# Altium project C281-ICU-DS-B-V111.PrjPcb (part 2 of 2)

## Sheet 06_Peripheral-C281-ICU-DS-B-V111.SchDoc: C281-ICU-DS-B-V100
size A1; Date: 2022/07/22; DrawnBy: 佟瑞泽; DocumentNumber: 6; Revision: V100; SheetNumber: 6; SheetTotal: 7
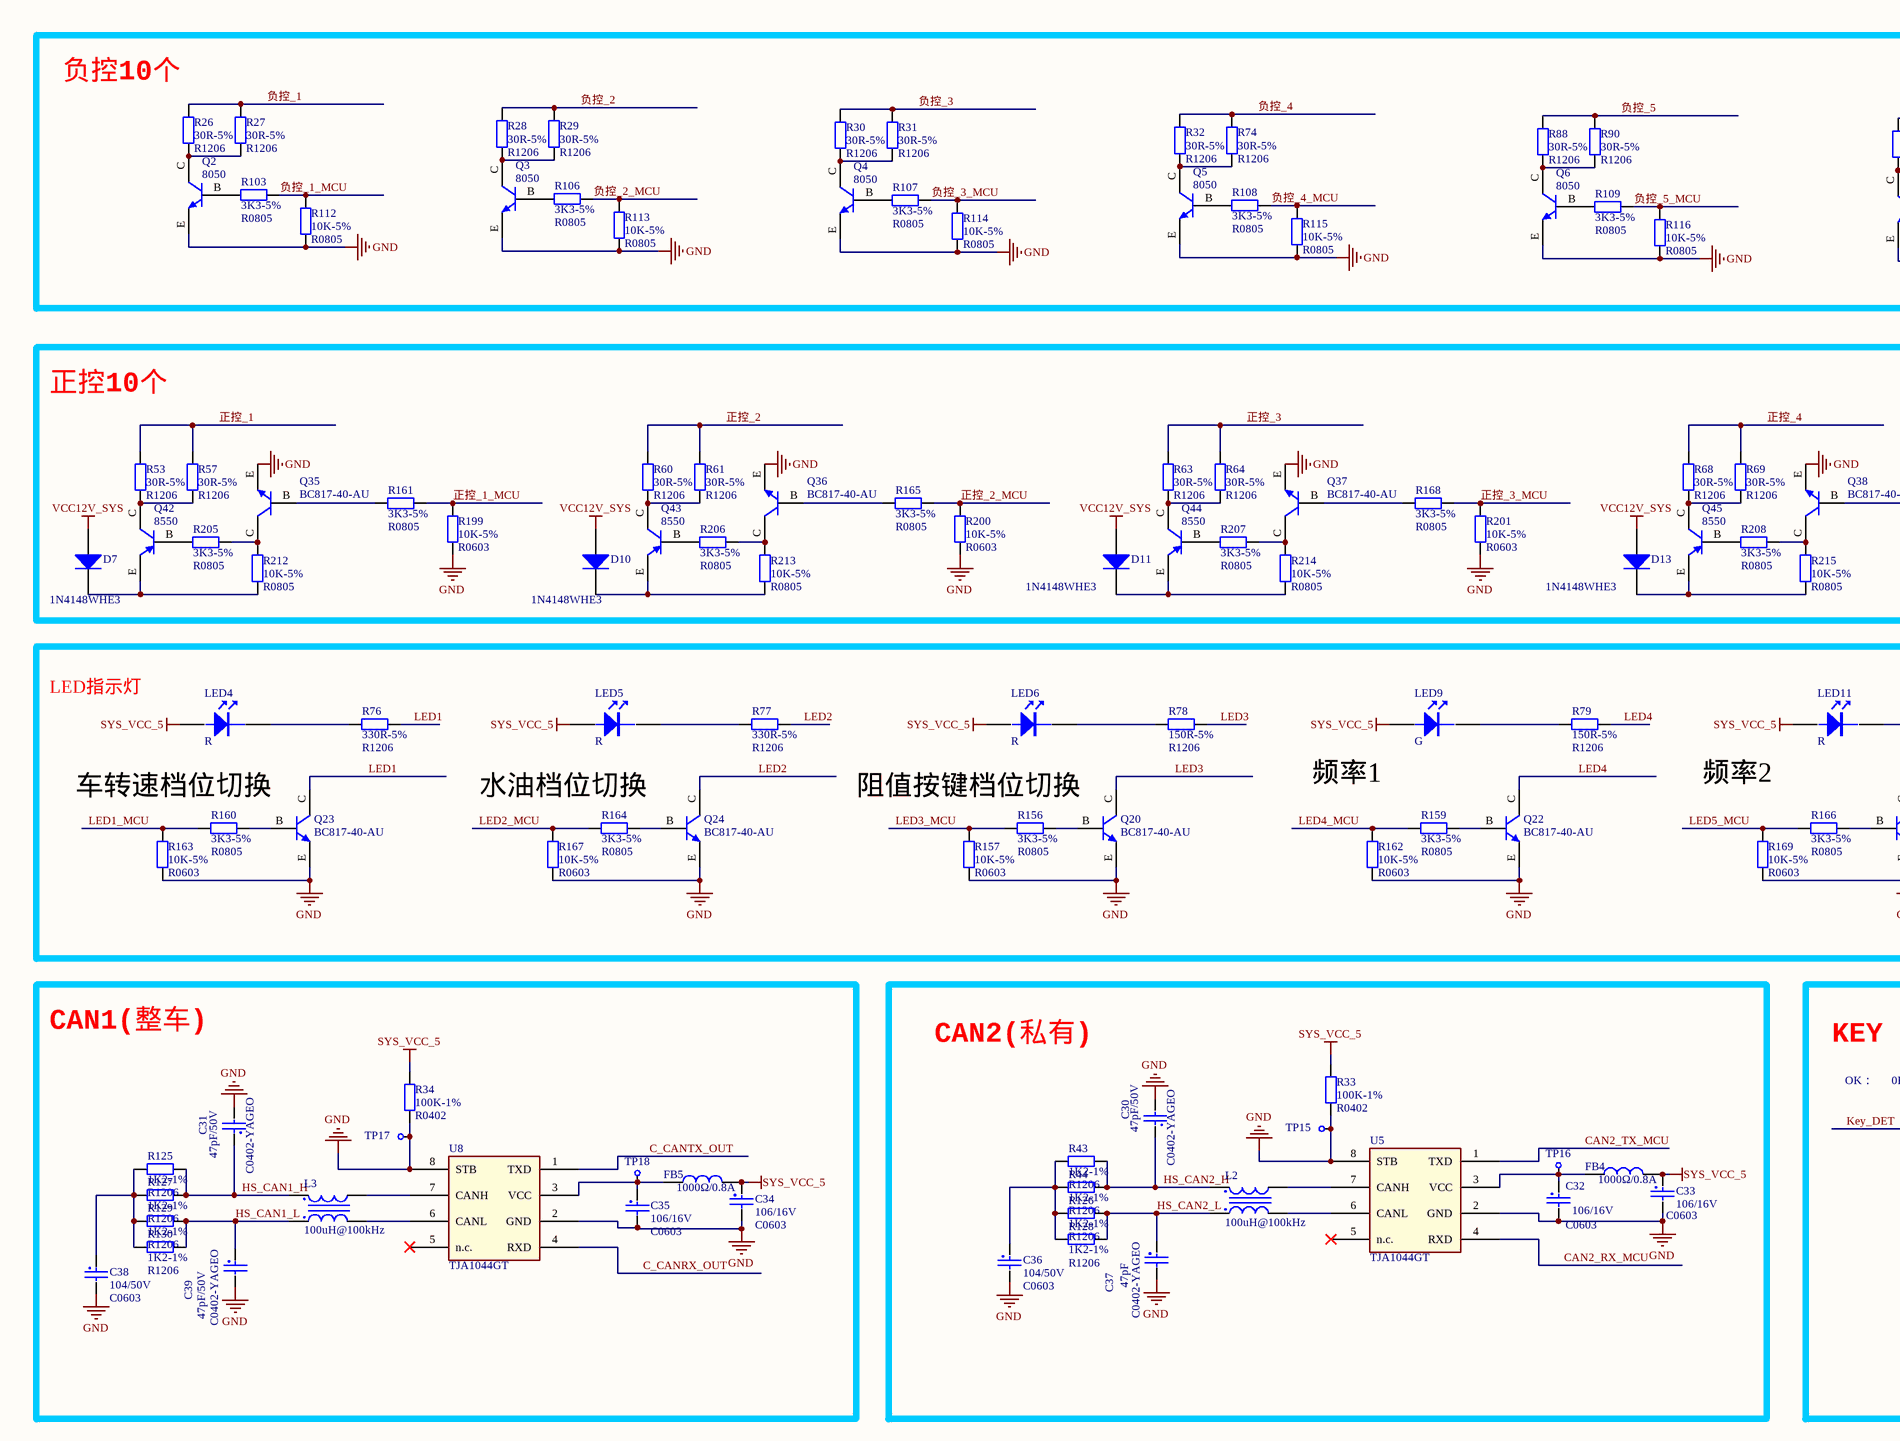
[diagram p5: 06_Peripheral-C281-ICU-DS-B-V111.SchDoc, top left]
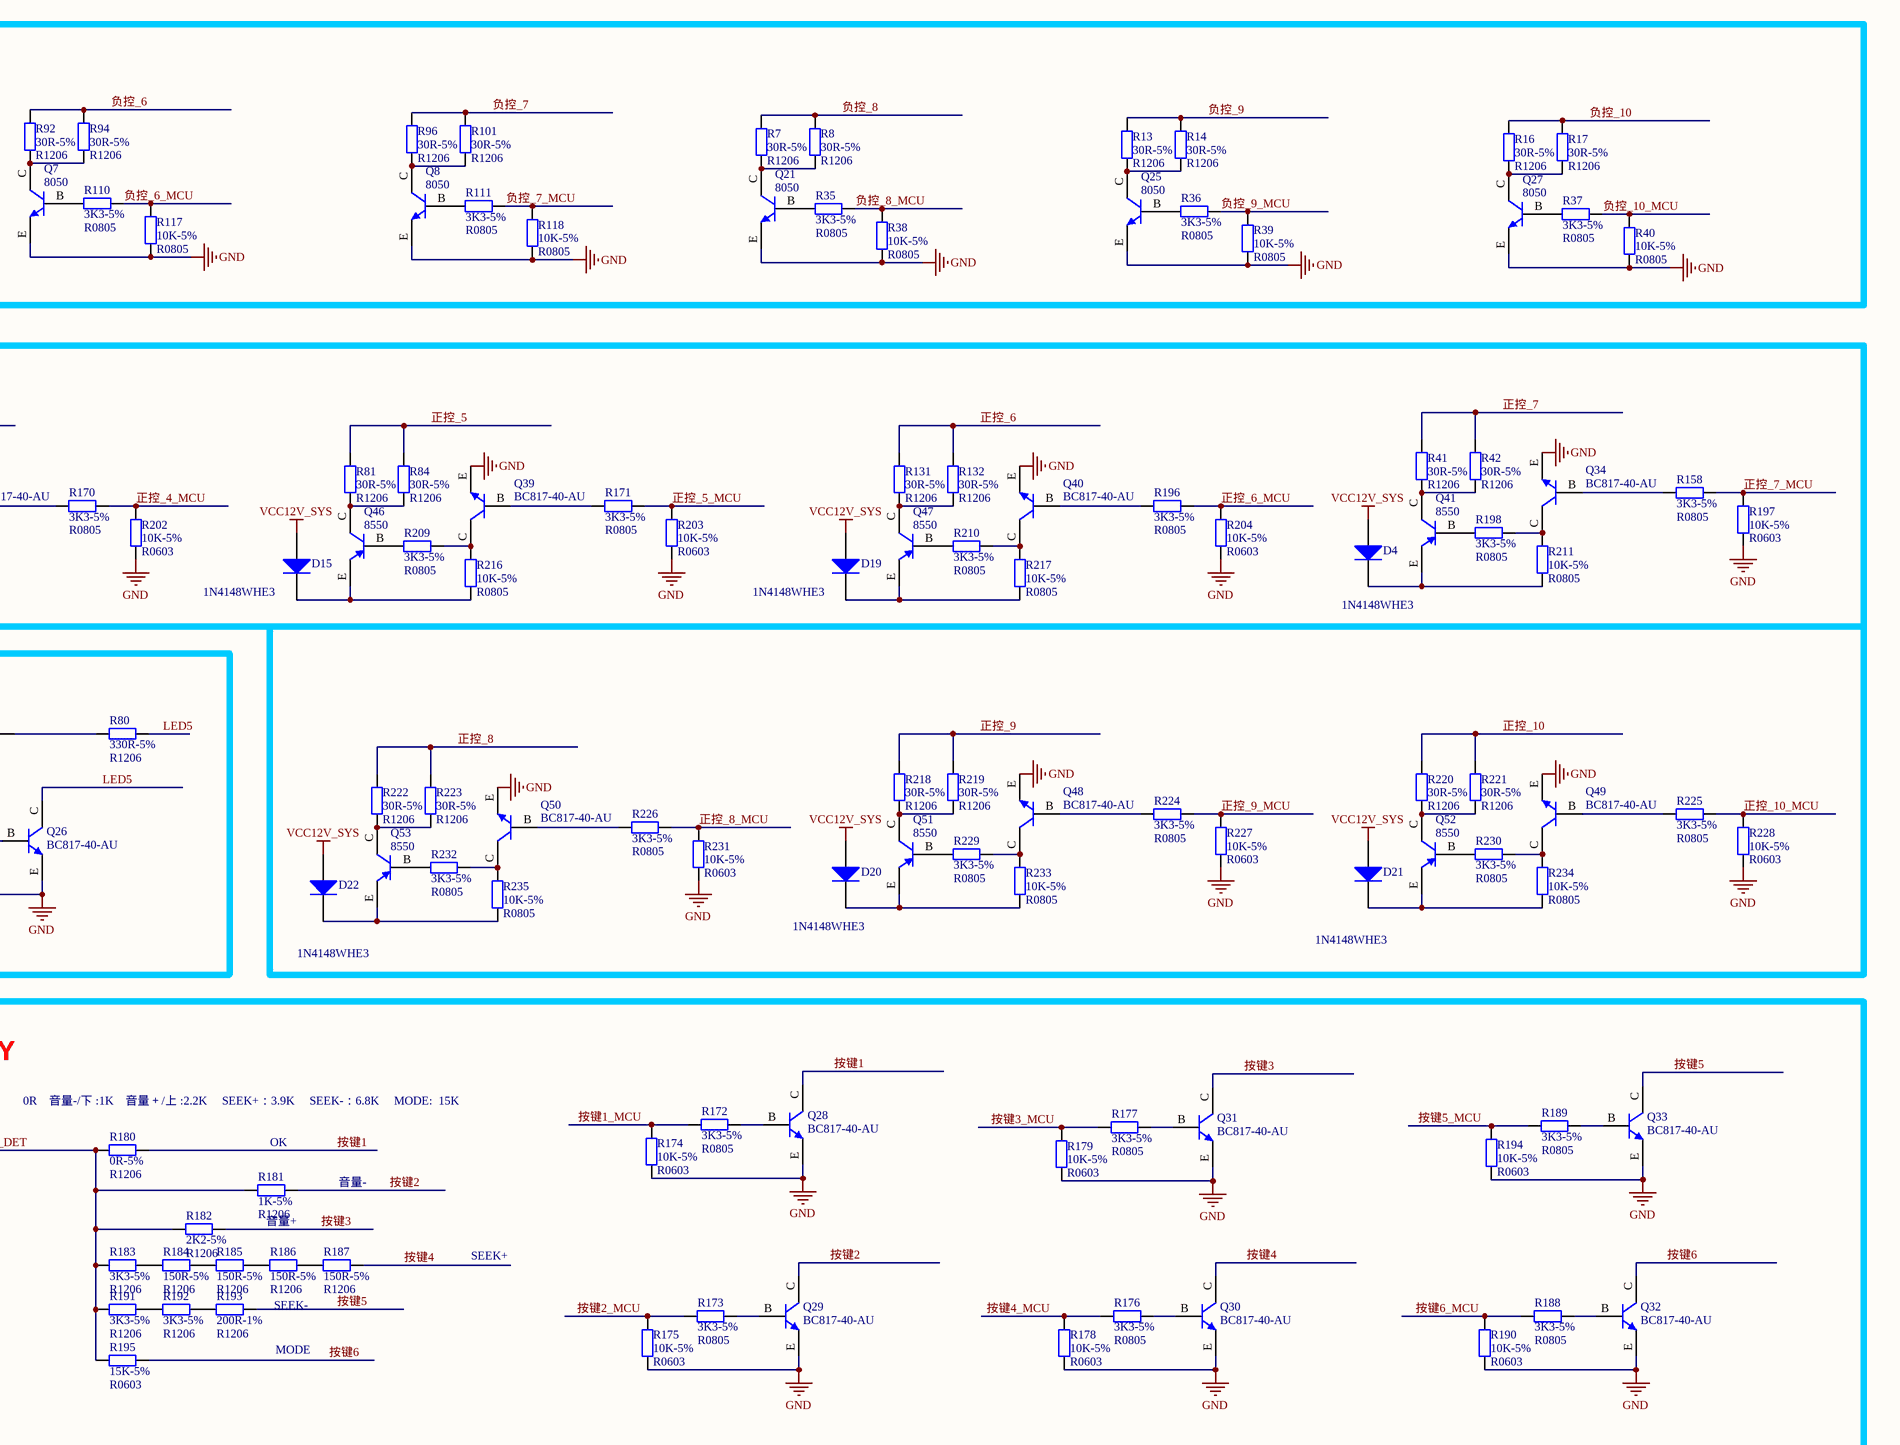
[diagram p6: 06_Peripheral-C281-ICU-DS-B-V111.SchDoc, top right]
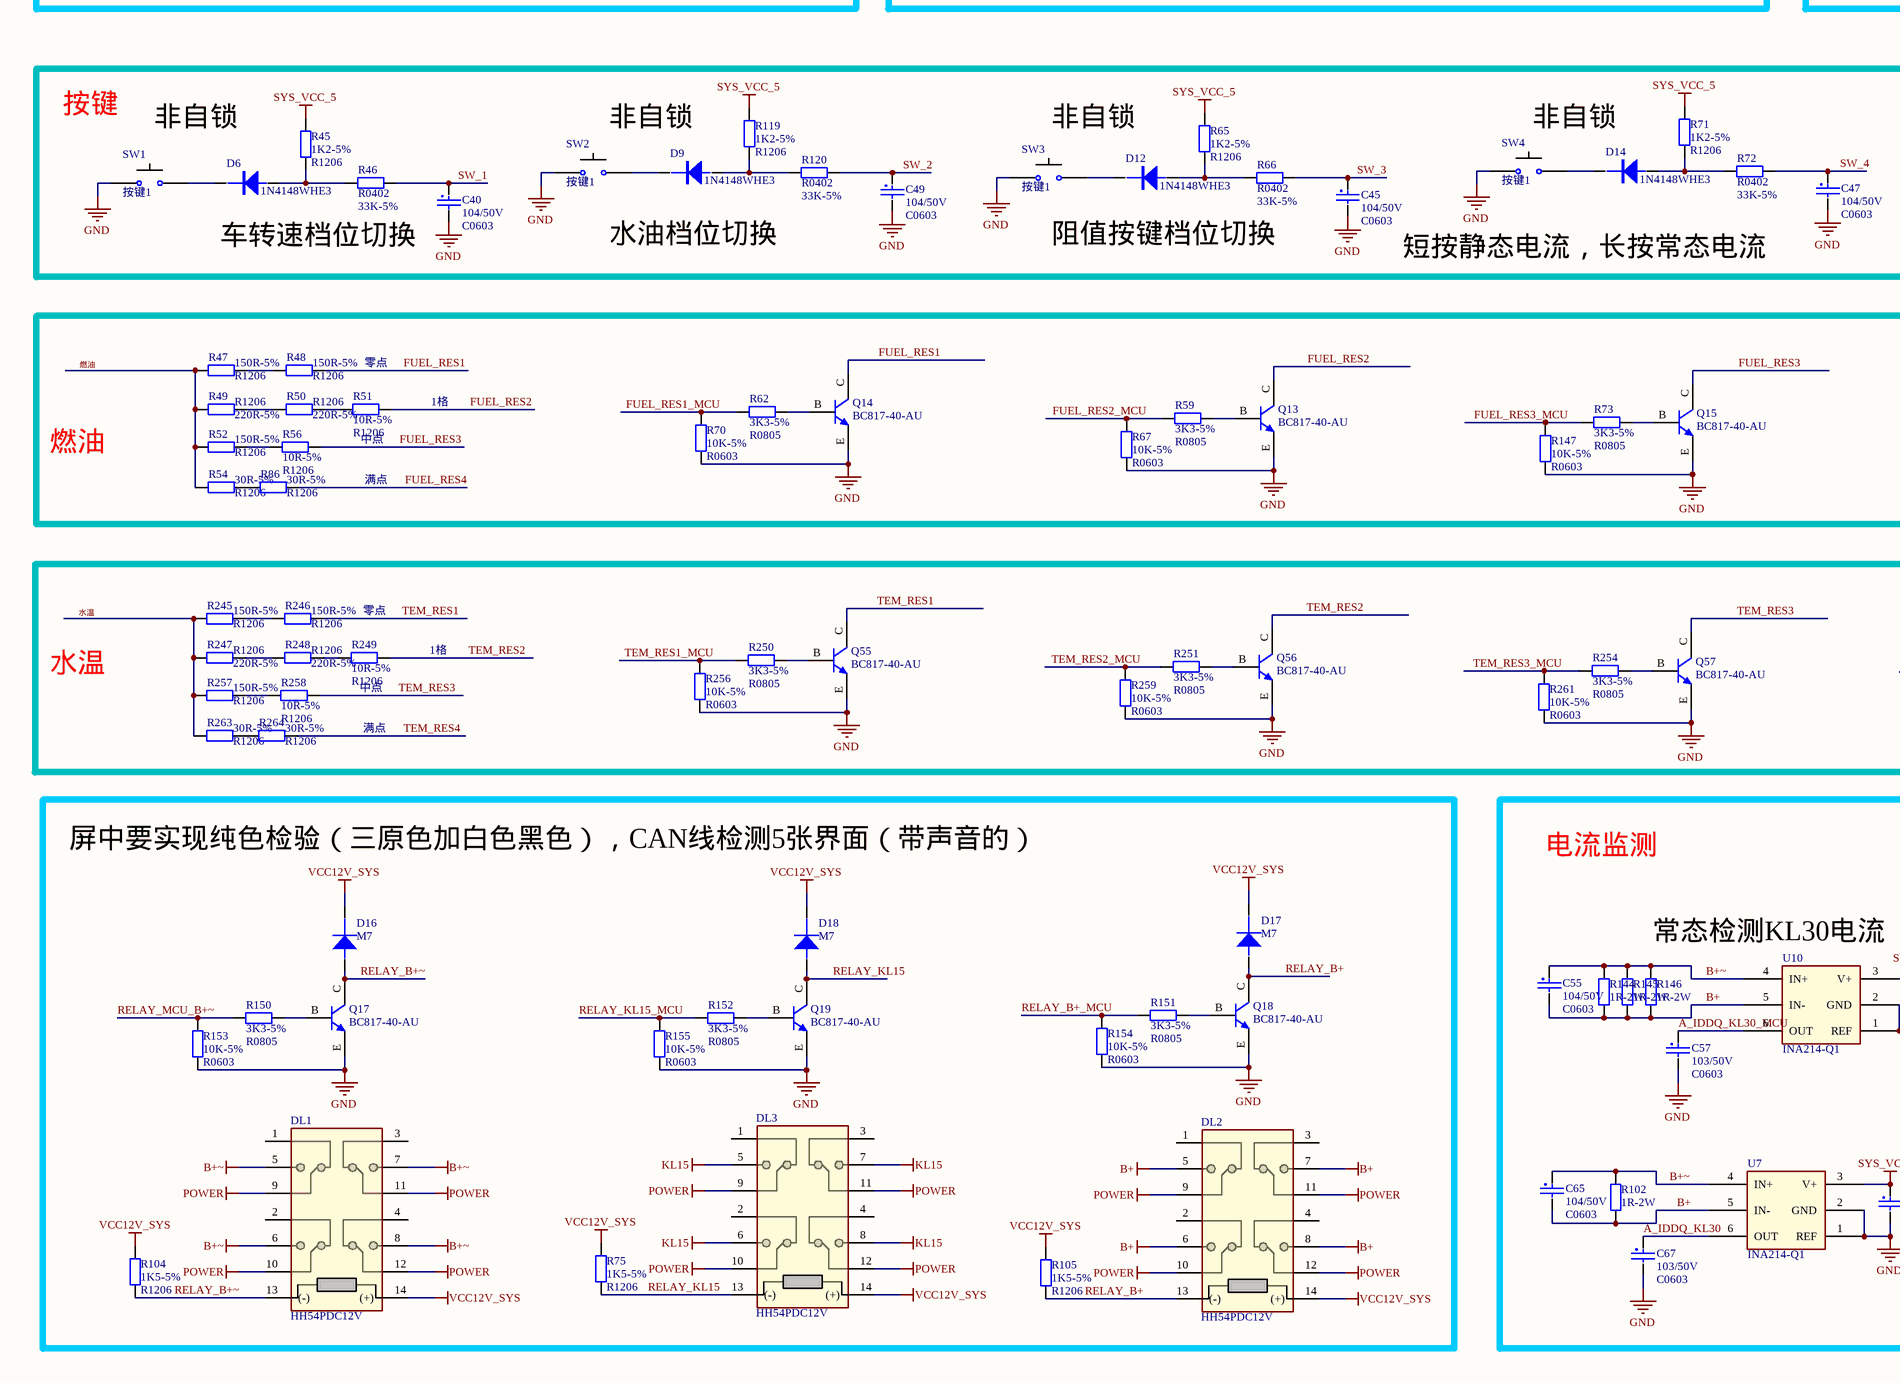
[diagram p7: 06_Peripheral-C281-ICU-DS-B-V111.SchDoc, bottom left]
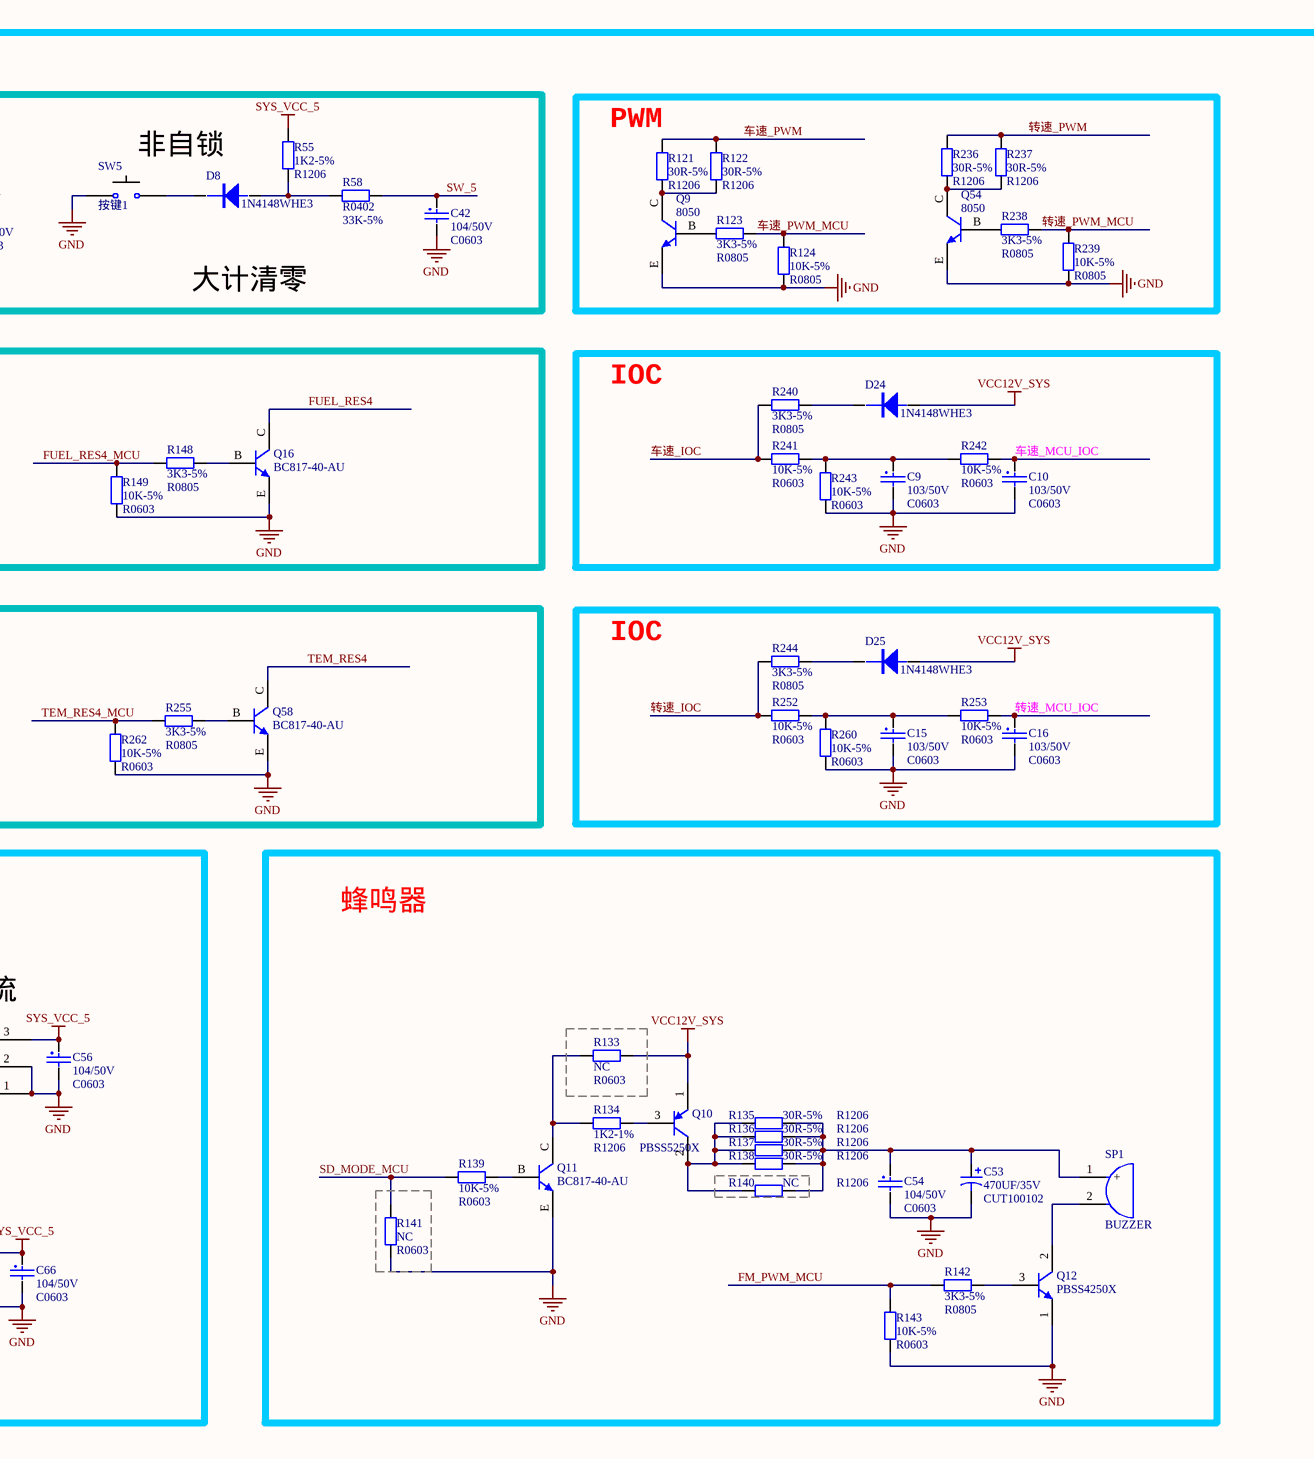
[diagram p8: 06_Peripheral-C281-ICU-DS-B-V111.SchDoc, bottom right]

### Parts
C9  value 103/50V  [C0603]  (hidden comment: 103)
C10  value 103/50V  [C0603]  (hidden comment: 103)
C15  value 103/50V  [C0603]  (hidden comment: 103)
C16  value 103/50V  [C0603]  (hidden comment: 103)
C30  value 47pF/50V  [C0402-YAGEO]  (hidden comment: 47pF)
C31  value 47pF/50V  [C0402-YAGEO]  (hidden comment: 47pF)
C32  value 106/16V  Footprint: C0603  [C0603-YAGEO]  (hidden comment: 106-16V)
C33  value 106/16V  Footprint: C0603  [C0603-YAGEO]  (hidden comment: 106-16V)
C34  value 106/16V  Footprint: C0603  [C0603-YAGEO]  (hidden comment: 106-16V)
C35  value 106/16V  Footprint: C0603  [C0603-YAGEO]  (hidden comment: 106-16V)
C36  value 104/50V  Footprint: C0603  [C0603-YAGEO]  (hidden comment: 104)
C37  47pF  [C0402-YAGEO]
C38  value 104/50V  Footprint: C0603  [C0603-YAGEO]  (hidden comment: 104)
C39  value 47pF/50V  [C0402-YAGEO]  (hidden comment: 47pF)
C40  value 104/50V  [C0603]  (hidden comment: 104)
C42  value 104/50V  [C0603]  (hidden comment: 104)
C45  value 104/50V  [C0603]  (hidden comment: 104)
C47  value 104/50V  [C0603]  (hidden comment: 104)
C49  value 104/50V  [C0603]  (hidden comment: 104)
C53  value 470UF/35V  [CUT100102]  (hidden comment: 470uF-35V)
C54  value 104/50V  [C0603]  (hidden comment: 104)
C55  value 104/50V  [C0603]  (hidden comment: 104)
C56  value 104/50V  [C0603]  (hidden comment: 104)
C57  value 103/50V  [C0603]  (hidden comment: 103)
C65  value 104/50V  [C0603]  (hidden comment: 104)
C66  value 104/50V  [C0603]  (hidden comment: 104)
C67  value 103/50V  [C0603]  (hidden comment: 103)
D4  1N4148WHE3  [SOD-123]
D6  value 1N4148WHE3  [SOD-123]  (hidden comment: 1N4148WHE3-TP)
D7  1N4148WHE3  [SOD-123]
D8  value 1N4148WHE3  [SOD-123]  (hidden comment: 1N4148WHE3-TP)
D9  value 1N4148WHE3  [SOD-123]  (hidden comment: 1N4148WHE3-TP)
D10  1N4148WHE3  [SOD-123]
D11  1N4148WHE3  [SOD-123]
D12  value 1N4148WHE3  [SOD-123]  (hidden comment: 1N4148WHE3-TP)
D13  1N4148WHE3  [SOD-123]
D14  value 1N4148WHE3  [SOD-123]  (hidden comment: 1N4148WHE3-TP)
D15  1N4148WHE3  [SOD-123]
D16  M7  [DO-214AC]
D17  M7  [DO-214AC]
D18  M7  [DO-214AC]
D19  1N4148WHE3  [SOD-123]
D20  1N4148WHE3  [SOD-123]
D21  1N4148WHE3  [SOD-123]
D22  1N4148WHE3  [SOD-123]
D24  value 1N4148WHE3  [SOD-123]  (hidden comment: 1N4148WHE3-TP)
D25  value 1N4148WHE3  [SOD-123]  (hidden comment: 1N4148WHE3-TP)
DL1  HH54PDC12V  [HH54PDC12V]
DL2  HH54PDC12V  [HH54PDC12V]
DL3  HH54PDC12V  [HH54PDC12V]
FB4  value 1000Ω/0.8A  [BLM18PG600SH1]  (hidden comment: 1000@100MHz)
FB5  value 1000Ω/0.8A  [BLM18PG600SH1]  (hidden comment: 1000@100MHz)
L2  value 100uH@100kHz  [DLW43SH101XK2]  (hidden comment: ACT45C-101-2P-TL000)
L3  value 100uH@100kHz  [DLW43SH101XK2]  (hidden comment: ACT45C-101-2P-TL000)
LED4  R  [LED]
LED5  R  [LED]
LED6  R  [LED]
LED9  G  [LED]
LED11  R  [LED]
Q2  8050  [SOT-89-3]
Q3  8050  [SOT-89-3]
Q4  8050  [SOT-89-3]
Q5  8050  [SOT-89-3]
Q6  8050  [SOT-89-3]
Q7  8050  [SOT-89-3]
Q8  8050  [SOT-89-3]
Q9  8050  [SOT-89-3]
Q10  PBSS5250X  [SOT-89]
Q11  BC817-40-AU  [SOT-23]
Q12  PBSS4250X  [SOT-89]
Q13  BC817-40-AU  [SOT-23]
Q14  BC817-40-AU  [SOT-23]
Q15  BC817-40-AU  [SOT-23]
Q16  BC817-40-AU  [SOT-23]
Q17  BC817-40-AU  [SOT-23]
Q18  BC817-40-AU  [SOT-23]
Q19  BC817-40-AU  [SOT-23]
Q20  BC817-40-AU  [SOT-23]
Q21  8050  [SOT-89-3]
Q22  BC817-40-AU  [SOT-23]
Q23  BC817-40-AU  [SOT-23]
Q24  BC817-40-AU  [SOT-23]
Q25  8050  [SOT-89-3]
Q26  BC817-40-AU  [SOT-23]
Q27  8050  [SOT-89-3]
Q28  BC817-40-AU  [SOT-23]
Q29  BC817-40-AU  [SOT-23]
Q30  BC817-40-AU  [SOT-23]
Q31  BC817-40-AU  [SOT-23]
Q32  BC817-40-AU  [SOT-23]
Q33  BC817-40-AU  [SOT-23]
Q34  BC817-40-AU  [SOT-23]
Q35  BC817-40-AU  [SOT-23]
Q36  BC817-40-AU  [SOT-23]
Q37  BC817-40-AU  [SOT-23]
Q38  BC817-40-AU  [SOT-23]
Q39  BC817-40-AU  [SOT-23]
Q40  BC817-40-AU  [SOT-23]
Q41  8550  [SOT-89-3]
Q42  8550  [SOT-89-3]
Q43  8550  [SOT-89-3]
Q44  8550  [SOT-89-3]
Q45  8550  [SOT-89-3]
Q46  8550  [SOT-89-3]
Q47  8550  [SOT-89-3]
Q48  BC817-40-AU  [SOT-23]
Q49  BC817-40-AU  [SOT-23]
Q50  BC817-40-AU  [SOT-23]
Q51  8550  [SOT-89-3]
Q52  8550  [SOT-89-3]
Q53  8550  [SOT-89-3]
Q54  8050  [SOT-89-3]
Q55  BC817-40-AU  [SOT-23]
Q56  BC817-40-AU  [SOT-23]
Q57  BC817-40-AU  [SOT-23]
Q58  BC817-40-AU  [SOT-23]
R7  value 30R-5%  [R1206]  (hidden comment: 30R)
R8  value 30R-5%  [R1206]  (hidden comment: 30R)
R13  value 30R-5%  [R1206]  (hidden comment: 30R)
R14  value 30R-5%  [R1206]  (hidden comment: 30R)
R16  value 30R-5%  [R1206]  (hidden comment: 30R)
R17  value 30R-5%  [R1206]  (hidden comment: 30R)
R26  value 30R-5%  [R1206]  (hidden comment: 30R)
R27  value 30R-5%  [R1206]  (hidden comment: 30R)
R28  value 30R-5%  [R1206]  (hidden comment: 30R)
R29  value 30R-5%  [R1206]  (hidden comment: 30R)
R30  value 30R-5%  [R1206]  (hidden comment: 30R)
R31  value 30R-5%  [R1206]  (hidden comment: 30R)
R32  value 30R-5%  [R1206]  (hidden comment: 30R)
R33  value 100K-1%  Footprint: R0402  [R0402-YAGEO]  (hidden comment: 100K-J)
R34  value 100K-1%  Footprint: R0402  [R0402-YAGEO]  (hidden comment: 100K-J)
R35  value 3K3-5%  [R0805]  (hidden comment: 3K3)
R36  value 3K3-5%  [R0805]  (hidden comment: 3K3)
R37  value 3K3-5%  [R0805]  (hidden comment: 3K3)
R38  value 10K-5%  [R0805]  (hidden comment: 10K)
R39  value 10K-5%  [R0805]  (hidden comment: 10K)
R40  value 10K-5%  [R0805]  (hidden comment: 10K)
R41  value 30R-5%  [R1206]  (hidden comment: 30R)
R42  value 30R-5%  [R1206]  (hidden comment: 30R)
R43  value 1K2-1%  Footprint: R1206  [R1206-YAGEO]  (hidden comment: 1K2-J)
R44  value 1K2-1%  Footprint: R1206  [R1206-YAGEO]  (hidden comment: 1K2-J)
R45  value 1K2-5%  [R1206]  (hidden comment: 1K2)
R46  value 33K-5%  [R0402]  (hidden comment: 33K)
R47  value 150R-5%  [R1206]  (hidden comment: 150R)
R48  value 150R-5%  [R1206]  (hidden comment: 150R)
R49  value 220R-5%  [R1206]  (hidden comment: 220R)
R50  value 220R-5%  [R1206]  (hidden comment: 220R)
R51  value 10R-5%  Footprint: R1206  [R1206-YAGEO]  (hidden comment: 10R)
R52  value 150R-5%  [R1206]  (hidden comment: 150R)
R53  value 30R-5%  [R1206]  (hidden comment: 30R)
R54  value 30R-5%  [R1206]  (hidden comment: 30R)
R55  value 1K2-5%  [R1206]  (hidden comment: 1K2)
R56  value 10R-5%  Footprint: R1206  [R1206-YAGEO]  (hidden comment: 10R)
R57  value 30R-5%  [R1206]  (hidden comment: 30R)
R58  value 33K-5%  [R0402]  (hidden comment: 33K)
R59  value 3K3-5%  [R0805]  (hidden comment: 3K3)
R60  value 30R-5%  [R1206]  (hidden comment: 30R)
R61  value 30R-5%  [R1206]  (hidden comment: 30R)
R62  value 3K3-5%  [R0805]  (hidden comment: 3K3)
R63  value 30R-5%  [R1206]  (hidden comment: 30R)
R64  value 30R-5%  [R1206]  (hidden comment: 30R)
R65  value 1K2-5%  [R1206]  (hidden comment: 1K2)
R66  value 33K-5%  [R0402]  (hidden comment: 33K)
R67  value 10K-5%  [R0603]  (hidden comment: 10K)
R68  value 30R-5%  [R1206]  (hidden comment: 30R)
R69  value 30R-5%  [R1206]  (hidden comment: 30R)
R70  value 10K-5%  [R0603]  (hidden comment: 10K)
R71  value 1K2-5%  [R1206]  (hidden comment: 1K2)
R72  value 33K-5%  [R0402]  (hidden comment: 33K)
R73  value 3K3-5%  [R0805]  (hidden comment: 3K3)
R74  value 30R-5%  [R1206]  (hidden comment: 30R)
R75  value 1K5-5%  [R1206]  (hidden comment: 1K5)
R76  value 330R-5%  [R1206]  (hidden comment: 330R)
R77  value 330R-5%  [R1206]  (hidden comment: 330R)
R78  value 150R-5%  [R1206]  (hidden comment: 150R)
R79  value 150R-5%  [R1206]  (hidden comment: 150R)
R80  value 330R-5%  [R1206]  (hidden comment: 330R)
R81  value 30R-5%  [R1206]  (hidden comment: 30R)
R84  value 30R-5%  [R1206]  (hidden comment: 30R)
R86  value 30R-5%  [R1206]  (hidden comment: 30R)
R88  value 30R-5%  [R1206]  (hidden comment: 30R)
R90  value 30R-5%  [R1206]  (hidden comment: 30R)
R92  value 30R-5%  [R1206]  (hidden comment: 30R)
R94  value 30R-5%  [R1206]  (hidden comment: 30R)
R96  value 30R-5%  [R1206]  (hidden comment: 30R)
R101  value 30R-5%  [R1206]  (hidden comment: 30R)
R102  1R-2W  [2WR]
R103  value 3K3-5%  [R0805]  (hidden comment: 3K3)
R104  value 1K5-5%  [R1206]  (hidden comment: 1K5)
R105  value 1K5-5%  [R1206]  (hidden comment: 1K5)
R106  value 3K3-5%  [R0805]  (hidden comment: 3K3)
R107  value 3K3-5%  [R0805]  (hidden comment: 3K3)
R108  value 3K3-5%  [R0805]  (hidden comment: 3K3)
R109  value 3K3-5%  [R0805]  (hidden comment: 3K3)
R110  value 3K3-5%  [R0805]  (hidden comment: 3K3)
R111  value 3K3-5%  [R0805]  (hidden comment: 3K3)
R112  value 10K-5%  [R0805]  (hidden comment: 10K)
R113  value 10K-5%  [R0805]  (hidden comment: 10K)
R114  value 10K-5%  [R0805]  (hidden comment: 10K)
R115  value 10K-5%  [R0805]  (hidden comment: 10K)
R116  value 10K-5%  [R0805]  (hidden comment: 10K)
R117  value 10K-5%  [R0805]  (hidden comment: 10K)
R118  value 10K-5%  [R0805]  (hidden comment: 10K)
R119  value 1K2-5%  [R1206]  (hidden comment: 1K2)
R120  value 33K-5%  [R0402]  (hidden comment: 33K)
R121  value 30R-5%  [R1206]  (hidden comment: 30R)
R122  value 30R-5%  [R1206]  (hidden comment: 30R)
R123  value 3K3-5%  [R0805]  (hidden comment: 3K3)
R124  value 10K-5%  [R0805]  (hidden comment: 10K)
R125  value 1K2-1%  Footprint: R1206  [R1206-YAGEO]  (hidden comment: 1K2-J)
R126  value 1K2-1%  Footprint: R1206  [R1206-YAGEO]  (hidden comment: 1K2-J)
R127  value 1K2-1%  Footprint: R1206  [R1206-YAGEO]  (hidden comment: 1K2-J)
R128  value 1K2-1%  Footprint: R1206  [R1206-YAGEO]  (hidden comment: 1K2-J)
R129  value 1K2-1%  Footprint: R1206  [R1206-YAGEO]  (hidden comment: 1K2-J)
R130  value 1K2-1%  Footprint: R1206  [R1206-YAGEO]  (hidden comment: 1K2-J)
R131  value 30R-5%  [R1206]  (hidden comment: 30R)
R132  value 30R-5%  [R1206]  (hidden comment: 30R)
R133  NC  [R0603]
R134  value 1K2-1%  [R1206]  (hidden comment: 1K2-J)
R135  value 30R-5%  [R1206]  (hidden comment: 30R)
R136  value 30R-5%  [R1206]  (hidden comment: 30R)
R137  value 30R-5%  [R1206]  (hidden comment: 30R)
R138  value 30R-5%  [R1206]  (hidden comment: 30R)
R139  value 10K-5%  [R0603]  (hidden comment: 10K)
R140  NC  [R1206]
R141  NC  [R0603]
R142  value 3K3-5%  [R0805]  (hidden comment: 3K3)
R143  value 10K-5%  [R0603]  (hidden comment: 10K)
R144  1R-2W  [2WR]
R145  1R-2W  [2WR]
R146  1R-2W  [2WR]
R147  value 10K-5%  [R0603]  (hidden comment: 10K)
R148  value 3K3-5%  [R0805]  (hidden comment: 3K3)
R149  value 10K-5%  [R0603]  (hidden comment: 10K)
R150  value 3K3-5%  [R0805]  (hidden comment: 3K3)
R151  value 3K3-5%  [R0805]  (hidden comment: 3K3)
R152  value 3K3-5%  [R0805]  (hidden comment: 3K3)
R153  value 10K-5%  [R0603]  (hidden comment: 10K)
R154  value 10K-5%  [R0603]  (hidden comment: 10K)
R155  value 10K-5%  [R0603]  (hidden comment: 10K)
R156  value 3K3-5%  [R0805]  (hidden comment: 3K3)
R157  value 10K-5%  [R0603]  (hidden comment: 10K)
R158  value 3K3-5%  [R0805]  (hidden comment: 3K3)
R159  value 3K3-5%  [R0805]  (hidden comment: 3K3)
R160  value 3K3-5%  [R0805]  (hidden comment: 3K3)
R161  value 3K3-5%  [R0805]  (hidden comment: 3K3)
R162  value 10K-5%  [R0603]  (hidden comment: 10K)
R163  value 10K-5%  [R0603]  (hidden comment: 10K)
R164  value 3K3-5%  [R0805]  (hidden comment: 3K3)
R165  value 3K3-5%  [R0805]  (hidden comment: 3K3)
R166  value 3K3-5%  [R0805]  (hidden comment: 3K3)
R167  value 10K-5%  [R0603]  (hidden comment: 10K)
R168  value 3K3-5%  [R0805]  (hidden comment: 3K3)
R169  value 10K-5%  [R0603]  (hidden comment: 10K)
R170  value 3K3-5%  [R0805]  (hidden comment: 3K3)
R171  value 3K3-5%  [R0805]  (hidden comment: 3K3)
R172  value 3K3-5%  [R0805]  (hidden comment: 3K3)
R173  value 3K3-5%  [R0805]  (hidden comment: 3K3)
R174  value 10K-5%  [R0603]  (hidden comment: 10K)
R175  value 10K-5%  [R0603]  (hidden comment: 10K)
R176  value 3K3-5%  [R0805]  (hidden comment: 3K3)
R177  value 3K3-5%  [R0805]  (hidden comment: 3K3)
R178  value 10K-5%  [R0603]  (hidden comment: 10K)
R179  value 10K-5%  [R0603]  (hidden comment: 10K)
R180  value 0R-5%  [R1206]  (hidden comment: 0R)
R181  value 1K-5%  [R1206]  (hidden comment: 1K)
R182  value 2K2-5%  [R1206]  (hidden comment: 2K2)
R183  value 3K3-5%  [R1206]  (hidden comment: 3K3)
R184  value 150R-5%  [R1206]  (hidden comment: 150R)
R185  value 150R-5%  [R1206]  (hidden comment: 150R)
R186  value 150R-5%  [R1206]  (hidden comment: 150R)
R187  value 150R-5%  [R1206]  (hidden comment: 150R)
R188  value 3K3-5%  [R0805]  (hidden comment: 3K3)
R189  value 3K3-5%  [R0805]  (hidden comment: 3K3)
R190  value 10K-5%  [R0603]  (hidden comment: 10K)
R191  value 3K3-5%  [R1206]  (hidden comment: 3K3)
R192  value 3K3-5%  [R1206]  (hidden comment: 3K3)
R193  value 200R-1%  [R1206]  (hidden comment: 200R-J)
R194  value 10K-5%  [R0603]  (hidden comment: 10K)
R195  value 15K-5%  [R0603]  (hidden comment: 15K)
R196  value 3K3-5%  [R0805]  (hidden comment: 3K3)
R197  value 10K-5%  [R0603]  (hidden comment: 10K)
R198  value 3K3-5%  [R0805]  (hidden comment: 3K3)
R199  value 10K-5%  [R0603]  (hidden comment: 10K)
R200  value 10K-5%  [R0603]  (hidden comment: 10K)
R201  value 10K-5%  [R0603]  (hidden comment: 10K)
R202  value 10K-5%  [R0603]  (hidden comment: 10K)
R203  value 10K-5%  [R0603]  (hidden comment: 10K)
R204  value 10K-5%  [R0603]  (hidden comment: 10K)
R205  value 3K3-5%  [R0805]  (hidden comment: 3K3)
R206  value 3K3-5%  [R0805]  (hidden comment: 3K3)
R207  value 3K3-5%  [R0805]  (hidden comment: 3K3)
R208  value 3K3-5%  [R0805]  (hidden comment: 3K3)
R209  value 3K3-5%  [R0805]  (hidden comment: 3K3)
R210  value 3K3-5%  [R0805]  (hidden comment: 3K3)
R211  value 10K-5%  [R0805]  (hidden comment: 10K)
R212  value 10K-5%  [R0805]  (hidden comment: 10K)
R213  value 10K-5%  [R0805]  (hidden comment: 10K)
R214  value 10K-5%  [R0805]  (hidden comment: 10K)
R215  value 10K-5%  [R0805]  (hidden comment: 10K)
R216  value 10K-5%  [R0805]  (hidden comment: 10K)
R217  value 10K-5%  [R0805]  (hidden comment: 10K)
R218  value 30R-5%  [R1206]  (hidden comment: 30R)
R219  value 30R-5%  [R1206]  (hidden comment: 30R)
R220  value 30R-5%  [R1206]  (hidden comment: 30R)
R221  value 30R-5%  [R1206]  (hidden comment: 30R)
R222  value 30R-5%  [R1206]  (hidden comment: 30R)
R223  value 30R-5%  [R1206]  (hidden comment: 30R)
R224  value 3K3-5%  [R0805]  (hidden comment: 3K3)
R225  value 3K3-5%  [R0805]  (hidden comment: 3K3)
R226  value 3K3-5%  [R0805]  (hidden comment: 3K3)
R227  value 10K-5%  [R0603]  (hidden comment: 10K)
R228  value 10K-5%  [R0603]  (hidden comment: 10K)
R229  value 3K3-5%  [R0805]  (hidden comment: 3K3)
R230  value 3K3-5%  [R0805]  (hidden comment: 3K3)
R231  value 10K-5%  [R0603]  (hidden comment: 10K)
R232  value 3K3-5%  [R0805]  (hidden comment: 3K3)
R233  value 10K-5%  [R0805]  (hidden comment: 10K)
R234  value 10K-5%  [R0805]  (hidden comment: 10K)
R235  value 10K-5%  [R0805]  (hidden comment: 10K)
R236  value 30R-5%  [R1206]  (hidden comment: 30R)
R237  value 30R-5%  [R1206]  (hidden comment: 30R)
R238  value 3K3-5%  [R0805]  (hidden comment: 3K3)
R239  value 10K-5%  [R0805]  (hidden comment: 10K)
R240  value 3K3-5%  [R0805]  (hidden comment: 3K3)
R241  value 10K-5%  [R0603]  (hidden comment: 10K)
R242  value 10K-5%  [R0603]  (hidden comment: 10K)
R243  value 10K-5%  [R0603]  (hidden comment: 10K)
R244  value 3K3-5%  [R0805]  (hidden comment: 3K3)
R245  value 150R-5%  [R1206]  (hidden comment: 150R)
R246  value 150R-5%  [R1206]  (hidden comment: 150R)
R247  value 220R-5%  [R1206]  (hidden comment: 220R)
R248  value 220R-5%  [R1206]  (hidden comment: 220R)
R249  value 10R-5%  Footprint: R1206  [R1206-YAGEO]  (hidden comment: 10R)
R250  value 3K3-5%  [R0805]  (hidden comment: 3K3)
R251  value 3K3-5%  [R0805]  (hidden comment: 3K3)
R252  value 10K-5%  [R0603]  (hidden comment: 10K)
R253  value 10K-5%  [R0603]  (hidden comment: 10K)
R254  value 3K3-5%  [R0805]  (hidden comment: 3K3)
R255  value 3K3-5%  [R0805]  (hidden comment: 3K3)
R256  value 10K-5%  [R0603]  (hidden comment: 10K)
R257  value 150R-5%  [R1206]  (hidden comment: 150R)
R258  value 10R-5%  Footprint: R1206  [R1206-YAGEO]  (hidden comment: 10R)
R259  value 10K-5%  [R0603]  (hidden comment: 10K)
R260  value 10K-5%  [R0603]  (hidden comment: 10K)
R261  value 10K-5%  [R0603]  (hidden comment: 10K)
R262  value 10K-5%  [R0603]  (hidden comment: 10K)
R263  value 30R-5%  [R1206]  (hidden comment: 30R)
R264  value 30R-5%  [R1206]  (hidden comment: 30R)
SP1  BUZZER  [FMQ(CN200)]
SW1  按键1  [SKPMAPE010]
SW2  按键1  [SKPMAPE010]
SW3  按键1  [SKPMAPE010]
SW4  按键1  [SKPMAPE010]
SW5  按键1  [SKPMAPE010]
TP15  1.0测试点  [TP1.0]  (value not drawn)
TP16  1.0测试点  [TP1.0]  (value not drawn)
TP17  1.0测试点  [TP1.0]  (value not drawn)
TP18  1.0测试点  [TP1.0]  (value not drawn)
U5  TJA1044GT  [SO-8]
U7  INA214-Q1  [INA214-Q1]
U8  TJA1044GT  [SO-8]
U10  INA214-Q1  [INA214-Q1]

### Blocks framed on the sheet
负控10个: Q2-Q8 Q21 Q25 Q27 R7 R8 R13 R14 R16 R17 R26-R32 R35-R40 R74 R88 R90 R92 R94 R96 R101 R103 R106-R118
正控10个: D4 D7 D10 D11 D13 D15 D19 Q34-Q47 R41 R42 R53 R57 R60 R61 R63 R64 R68 R69 R81 R84 R131 R132 R158 R161 R165 R168 R170 R171 R196-R217
CAN1(整车): C31 C34 C35 C38 C39 FB5 L3 R34 R125 R127 R129 R130 TP17 TP18 U8
CAN2(私有): C30 C32 C33 C36 C37 FB4 L2 R33 R43 R44 R126 R128 TP15 TP16 U5
KEY: Q28-Q33 R172-R195
PWM: Q9 Q54 R121-R124 R236-R239
燃油: Q13-Q16 R47-R52 R54 R56 R59 R62 R67 R70 R73 R86 R147-R149
IOC: C9 C10 D24 R240-R243
水温: Q55-Q58 R245-R251 R254-R259 R261-R264
IOC: C15 C16 D25 R244 R252 R253 R260
屏中要实现纯色检验（三原色加白色黑色），CAN线检测5张界面（带声音的）: D16-D18 DL1-DL3 Q17-Q19 R75 R104 R105 R150-R155
蜂鸣器: C53 C54 Q10-Q12 R133-R143 SP1

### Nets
B+: C55.2 C65.2 DL2.5 DL2.6 DL2.7 DL2.8 R102.1 R144.1 R145.1 R146.1 U7.5(IN-) U10.5(IN-)
B+~: C55.1 C65.1 DL1.5 DL1.6 DL1.7 DL1.8 R102.2 R144.2 R145.2 R146.2 U7.4(IN+) U10.4(IN+)
GND: C9.2 C10.2 C15.2 C16.2 C30.2 C31.2 C32.2 C33.2 C34.2 C35.2 C36.2 C37.2 C38.2 C39.2 C40.2 C42.2 C45.2 C47.2 C49.2 C53.2 C54.2 C56.2 C57.2 C66.2 C67.2 Q2.E Q3.E Q4.E Q5.E Q6.E Q7.E Q8.E Q9.E Q11.E Q12.1(E) Q13.E Q14.E Q15.E Q16.E Q17.E Q18.E Q19.E Q20.E Q21.E Q22.E Q23.E Q24.E Q25.E Q26.E Q27.E Q28.E Q29.E Q30.E Q31.E Q32.E Q33.E Q34.E Q35.E Q36.E Q37.E Q38.E Q39.E Q40.E Q48.E Q49.E Q50.E Q54.E Q55.E Q56.E Q57.E Q58.E R33.2 R34.2 R38.1 R39.1 R40.1 R67.1 R70.1 R112.1 R113.1 R114.1 R115.1 R116.1 R117.1 R118.1 R124.1 R141.1 R143.1 R147.1 R149.1 R153.1 R154.1 R155.1 R157.1 R162.1 R163.1 R167.1 R169.1 R174.1 R175.1 R178.1 R179.1 R190.1 R194.1 R197.1 R199.1 R200.1 R201.1 R202.1 R203.1 R204.1 R227.1 R228.1 R231.1 R239.1 R243.1 R256.1 R259.1 R260.1 R261.1 R262.1 SW1.1 SW2.1 SW3.1 SW4.1 SW5.1 TP15.1 TP17.1 U5.2(GND) U5.8(STB) U7.1(REF) U7.2(GND) U8.2(GND) U8.8(STB) U10.1(REF) U10.2(GND)
KL15: DL3.5 DL3.6 DL3.7 DL3.8
POWER: DL1.9 DL1.10 DL1.11 DL1.12 DL2.9 DL2.10 DL2.11 DL2.12 DL3.9 DL3.10 DL3.11 DL3.12
SYS_VCC_5: C33.1 C34.1 C56.1 C66.1 FB4.2 FB5.2 LED4.1 LED5.1 LED6.1 LED9.1 LED11.1 R33.1 R34.1 R45.2 R55.2 R65.2 R71.2 R119.2 U7.3(V+) U10.3(V+)
VCC12V_SYS: D4.1 D7.1 D10.1 D11.1 D13.1 D15.1 D16.2 D17.2 D18.2 D19.1 D20.1 D21.1 D22.1 D24.2 D25.2 DL1.14((+)) DL2.14((+)) DL3.14((+)) Q10.1(E) R75.2 R104.2 R105.2 R133.1
A_IDDQ_KL30: C67.1 U7.6(OUT)
A_IDDQ_KL30_MCU: C57.1 U10.6(OUT)
C_CANRX_OUT: U8.4(RXD)
C_CANTX_OUT: U8.1(TXD)
CAN2_RX_MCU: U5.4(RXD)
CAN2_TX_MCU: U5.1(TXD)
FM_PWM_MCU: R142.1 R143.2
FUEL_RES1: Q14.C R48.2
FUEL_RES1_MCU: R62.1 R70.2
FUEL_RES2: Q13.C R51.2
FUEL_RES2_MCU: R59.1 R67.2
FUEL_RES3: Q15.C R56.2
FUEL_RES3_MCU: R73.1 R147.2
FUEL_RES4: Q16.C R86.2
FUEL_RES4_MCU: R148.1 R149.2
HS_CAN1_H: C31.1 L3.4 R125.2 R127.2
HS_CAN1_L: C39.1 L3.1 R129.2 R130.2
HS_CAN2_H: C30.1 L2.4 R43.2 R44.2
HS_CAN2_L: C37.1 L2.1 R126.2 R128.2
Key_DET: R180.1 R181.1 R182.1 R183.1 R191.1 R195.1
LED1: Q23.C R76.2
LED1_MCU: R160.1 R163.2
LED2: Q24.C R77.2
LED2_MCU: R164.1 R167.2
LED3: Q20.C R78.2
LED3_MCU: R156.1 R157.2
LED4: Q22.C R79.2
LED4_MCU: R159.1 R162.2
LED5: Q26.C R80.2
LED5_MCU: R166.1 R169.2
RELAY_B+: D17.1 DL2.13((-)) Q18.C R105.1
RELAY_B+_MCU: R151.1 R154.2
RELAY_B+~: D16.1 DL1.13((-)) Q17.C R104.1
RELAY_KL15: D18.1 DL3.13((-)) Q19.C R75.1
RELAY_KL15_MCU: R152.1 R155.2
RELAY_MCU_B+~: R150.1 R153.2
SD_MODE_MCU: R139.1 R141.2
SW_1: C40.1 R46.2
SW_2: C49.1 R120.2
SW_3: C45.1 R66.2
SW_4: C47.1 R72.2
SW_5: C42.1 R58.2
TEM_RES1: Q55.C R246.2
TEM_RES1_MCU: R250.1 R256.2
TEM_RES2: Q56.C R249.2
TEM_RES2_MCU: R251.1 R259.2
TEM_RES3: Q57.C R258.2
TEM_RES3_MCU: R254.1 R261.2
TEM_RES4: Q58.C R264.2
TEM_RES4_MCU: R255.1 R262.2
按键1: Q28.C R180.2
按键1_MCU: R172.1 R174.2
按键2: Q29.C R181.2
按键2_MCU: R173.1 R175.2
按键3: Q31.C R182.2
按键3_MCU: R177.1 R179.2
按键4: Q30.C R187.2
按键4_MCU: R176.1 R178.2
按键5: Q33.C R193.2
按键5_MCU: R189.1 R194.2
按键6: Q32.C R195.2
按键6_MCU: R188.1 R190.2
正控_1: R53.2 R57.2
正控_1_MCU: R161.2 R199.2
正控_2: R60.2 R61.2
正控_2_MCU: R165.2 R200.2
正控_3: R63.2 R64.2
正控_3_MCU: R168.2 R201.2
正控_4: R68.2 R69.2
正控_4_MCU: R170.2 R202.2
正控_5: R81.2 R84.2
正控_5_MCU: R171.2 R203.2
正控_6: R131.2 R132.2
正控_6_MCU: R196.2 R204.2
正控_7: R41.2 R42.2
正控_7_MCU: R158.2 R197.2
正控_8: R222.2 R223.2
正控_8_MCU: R226.2 R231.2
正控_9: R218.2 R219.2
正控_9_MCU: R224.2 R227.2
正控_10: R220.2 R221.2
正控_10_MCU: R225.2 R228.2
水温: R245.1 R247.1 R257.1 R263.1
燃油: R47.1 R49.1 R52.1 R54.1
负控_1: R26.2 R27.2
负控_1_MCU: R103.2 R112.2
负控_2: R28.2 R29.2
负控_2_MCU: R106.2 R113.2
负控_3: R30.2 R31.2
负控_3_MCU: R107.2 R114.2
负控_4: R32.2 R74.2
负控_4_MCU: R108.2 R115.2
负控_5: R88.2 R90.2
负控_5_MCU: R109.2 R116.2
负控_6: R92.2 R94.2
负控_6_MCU: R110.2 R117.2
负控_7: R96.2 R101.2
负控_7_MCU: R111.2 R118.2
负控_8: R7.2 R8.2
负控_8_MCU: R35.2 R38.2
负控_9: R13.2 R14.2
负控_9_MCU: R36.2 R39.2
负控_10: R16.2 R17.2
负控_10_MCU: R37.2 R40.2
车速_IOC: R240.1 R241.2
车速_MCU_IOC: C10.1 R242.1
车速_PWM: R121.2 R122.2
车速_PWM_MCU: R123.2 R124.2
转速_IOC: R244.1 R252.2
转速_MCU_IOC: C16.1 R253.1
转速_PWM: R236.2 R237.2
转速_PWM_MCU: R238.2 R239.2
NetC9_1: C9.1 R241.1 R242.2 R243.2
NetC15_1: C15.1 R252.1 R253.2 R260.2
NetC32_1: C32.1 FB4.1 TP16.1 U5.3(VCC)
NetC35_1: C35.1 FB5.1 TP18.1 U8.3(VCC)
NetC36_1: C36.1 R43.1 R44.1 R126.1 R128.1
NetC38_1: C38.1 R125.1 R127.1 R129.1 R130.1
NetC53_1: C53.1 C54.1 R135.2 R136.2 R137.2 R138.2 R140.2 SP1.1(+)
NetD4_2: D4.2 Q41.E R211.1
NetD6_1: D6.1 SW1.2
NetD6_2: D6.2 R45.1 R46.1
NetD7_2: D7.2 Q42.E R212.1
NetD8_1: D8.1 SW5.2
NetD8_2: D8.2 R55.1 R58.1
NetD9_1: D9.1 SW2.2
NetD9_2: D9.2 R119.1 R120.1
NetD10_2: D10.2 Q43.E R213.1
NetD11_2: D11.2 Q44.E R214.1
NetD12_1: D12.1 SW3.2
NetD12_2: D12.2 R65.1 R66.1
NetD13_2: D13.2 Q45.E R215.1
NetD14_1: D14.1 SW4.2
NetD14_2: D14.2 R71.1 R72.1
NetD15_2: D15.2 Q46.E R216.1
NetD19_2: D19.2 Q47.E R217.1
NetD20_2: D20.2 Q51.E R233.1
NetD21_2: D21.2 Q52.E R234.1
NetD22_2: D22.2 Q53.E R235.1
NetD24_1: D24.1 R240.2
NetD25_1: D25.1 R244.2
NetL2_2: L2.2 U5.6(CANL)
NetL2_3: L2.3 U5.7(CANH)
NetL3_2: L3.2 U8.6(CANL)
NetL3_3: L3.3 U8.7(CANH)
NetLED4_2: LED4.2 R76.1
NetLED5_2: LED5.2 R77.1
NetLED6_2: LED6.2 R78.1
NetLED9_2: LED9.2 R79.1
NetLED11_2: LED11.2 R80.1
NetQ2_B: Q2.B R103.1
NetQ2_C: Q2.C R26.1 R27.1
NetQ3_B: Q3.B R106.1
NetQ3_C: Q3.C R28.1 R29.1
NetQ4_B: Q4.B R107.1
NetQ4_C: Q4.C R30.1 R31.1
NetQ5_B: Q5.B R108.1
NetQ5_C: Q5.C R32.1 R74.1
NetQ6_B: Q6.B R109.1
NetQ6_C: Q6.C R88.1 R90.1
NetQ7_B: Q7.B R110.1
NetQ7_C: Q7.C R92.1 R94.1
NetQ8_B: Q8.B R111.1
NetQ8_C: Q8.C R96.1 R101.1
NetQ9_B: Q9.B R123.1
NetQ9_C: Q9.C R121.1 R122.1
NetQ10_2: Q10.2(C) R135.1 R136.1 R137.1 R138.1 R140.1
NetQ10_3: Q10.3(B) R134.2
NetQ11_B: Q11.B R139.2
NetQ11_C: Q11.C R133.2 R134.1
NetQ12_2: Q12.2(C) SP1.2
NetQ12_3: Q12.3(B) R142.2
NetQ13_B: Q13.B R59.2
NetQ14_B: Q14.B R62.2
NetQ15_B: Q15.B R73.2
NetQ16_B: Q16.B R148.2
NetQ17_B: Q17.B R150.2
NetQ18_B: Q18.B R151.2
NetQ19_B: Q19.B R152.2
NetQ20_B: Q20.B R156.2
NetQ21_B: Q21.B R35.1
NetQ21_C: Q21.C R7.1 R8.1
NetQ22_B: Q22.B R159.2
NetQ23_B: Q23.B R160.2
NetQ24_B: Q24.B R164.2
NetQ25_B: Q25.B R36.1
NetQ25_C: Q25.C R13.1 R14.1
NetQ26_B: Q26.B R166.2
NetQ27_B: Q27.B R37.1
NetQ27_C: Q27.C R16.1 R17.1
NetQ28_B: Q28.B R172.2
NetQ29_B: Q29.B R173.2
NetQ30_B: Q30.B R176.2
NetQ31_B: Q31.B R177.2
NetQ32_B: Q32.B R188.2
NetQ33_B: Q33.B R189.2
NetQ34_B: Q34.B R158.1
NetQ34_C: Q34.C R198.2 R211.2
NetQ35_B: Q35.B R161.1
NetQ35_C: Q35.C R205.2 R212.2
NetQ36_B: Q36.B R165.1
NetQ36_C: Q36.C R206.2 R213.2
NetQ37_B: Q37.B R168.1
NetQ37_C: Q37.C R207.2 R214.2
NetQ38_B: Q38.B R170.1
NetQ38_C: Q38.C R208.2 R215.2
NetQ39_B: Q39.B R171.1
NetQ39_C: Q39.C R209.2 R216.2
NetQ40_B: Q40.B R196.1
NetQ40_C: Q40.C R210.2 R217.2
NetQ41_B: Q41.B R198.1
NetQ41_C: Q41.C R41.1 R42.1
NetQ42_B: Q42.B R205.1
NetQ42_C: Q42.C R53.1 R57.1
NetQ43_B: Q43.B R206.1
NetQ43_C: Q43.C R60.1 R61.1
NetQ44_B: Q44.B R207.1
NetQ44_C: Q44.C R63.1 R64.1
NetQ45_B: Q45.B R208.1
NetQ45_C: Q45.C R68.1 R69.1
NetQ46_B: Q46.B R209.1
NetQ46_C: Q46.C R81.1 R84.1
NetQ47_B: Q47.B R210.1
NetQ47_C: Q47.C R131.1 R132.1
NetQ48_B: Q48.B R224.1
NetQ48_C: Q48.C R229.2 R233.2
NetQ49_B: Q49.B R225.1
NetQ49_C: Q49.C R230.2 R234.2
NetQ50_B: Q50.B R226.1
NetQ50_C: Q50.C R232.2 R235.2
NetQ51_B: Q51.B R229.1
NetQ51_C: Q51.C R218.1 R219.1
NetQ52_B: Q52.B R230.1
NetQ52_C: Q52.C R220.1 R221.1
NetQ53_B: Q53.B R232.1
NetQ53_C: Q53.C R222.1 R223.1
NetQ54_B: Q54.B R238.1
NetQ54_C: Q54.C R236.1 R237.1
NetQ55_B: Q55.B R250.2
NetQ56_B: Q56.B R251.2
NetQ57_B: Q57.B R254.2
NetQ58_B: Q58.B R255.2
NetR47_2: R47.2 R48.1
NetR49_2: R49.2 R50.1
NetR50_2: R50.2 R51.1
NetR52_2: R52.2 R56.1
NetR54_2: R54.2 R86.1
NetR183_2: R183.2 R184.1
NetR184_2: R184.2 R185.1
NetR185_2: R185.2 R186.1
NetR186_2: R186.2 R187.1
NetR191_2: R191.2 R192.1
NetR192_2: R192.2 R193.1
NetR245_2: R245.2 R246.1
NetR247_2: R247.2 R248.1
NetR248_2: R248.2 R249.1
NetR257_2: R257.2 R258.1
NetR263_2: R263.2 R264.1

Not connected (* = marked no-connect by the designer): DL1 1 2 3 4; DL2 1 2 3 4; DL3 1 2 3 4; U5 5(n.c.)*; U8 5(n.c.)*

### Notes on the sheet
- LED指示灯
- 车转速档位切换
- 水油档位切换
- 阻值按键档位切换
- 频率1
- 频率2
- (near R180) OK：      0R    音量-/下 :1K    音量＋/上 :2.2K     SEEK+：3.9K     SEEK-：6.8K     MODE:  15K
- (near R181) OK
- 音量+
- 音量-
- SEEK+
- SEEK-
- (near R193) MODE
- 按键
- 非自锁
- 短按静态电流，长按常态电流
- 大计清零
- 零点
- (near R51) 中点
- 1格
- 满点
- (near R249) 中点
- 电流监测
- 常态检测KL30电流

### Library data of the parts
C9 C10 C15 C16 C57 C67 = C103-50V-C0603: CAP,103,50V,10%,C0603; Part Number: 30305028; Manufacture 1: FH; Manufacture 1 P/N: 0603B103K500NT; 代理/分销商: 四平市吉华高新技术有限公司
C30 C31 C39 = C47pF-50V-C0402-X: CAP,47pF,50V,10%,C0402; Part Number: 30305314; Manufacture 1: YAGEO; Manufacture 1 P/N: CC0402JRNPO9BN470; 代理/分销商: 厦门信和达电子有限公司
C32-C35 = C106-16V-C0603-X: CAP,106,16V,20%,C0603; Part Number: 30305207; Manufacture 1: YAGEO; Manufacture 1 P/N: CC0603MRX5R7BB106; 代理/分销商: 厦门信和达电子有限公司
C36 C38 = C104-50V-C0603-X: CAP,104,50V,10%,C0603; Part Number: 30305248; Manufacture 1: YAGEO; Manufacture 1 P/N: CC0603KRX7R9BB104; 代理/分销商: 厦门信和达电子有限公司
C37 = C47pF-50V-C0402-X: CAP,47pF,50V,10%,C0402; Part Number: 30305314; Manufacture 1: YAGEO; Manufacture 1 P/N: CC0402JRNPO9BN470; 代理/分销商: 厦门信和达电子有限公司; Value: 47pF/50V
C40 C42 C45 C47 C49 C54-C56 C65 C66 = C104-50V-C0603: CAP,104,50V,10%,C0603; Part Number: 30305029; Manufacture 1: FH; Manufacture 1 P/N: 0603B104K500NT; 代理/分销商: 四平市吉华高新技术有限公司
C53 = C470uF-35V-CUT100102: ECAP,470uF,35V,20%,φ10x10.2mm,SMD; Part Number: 30311004; Manufacture 1: KS; Manufacture 1 P/N: CS35V470UF; 代理/分销商: 北京圣基工贸公司/广东东联盛科技有限公司/东莞市柯森奥泰科技有限公司
D4 D7 D10 D11 D13 D15 D19-D22 = 1N4148WHE3: Diode,IFM=300mA,VR=100V,,VRRM=100V,SOD-123,3.85*1.8*1.35mm; Manufacture 1 P/N: 1N4148WHE3-TP; Part Number: 30307124; Manufacture 1: MCC美微科; 代理/分销商: 艾睿(中国)电子贸易有限公司; 元件名称: 贴片二极管1N4148ar（车规级）
D6 D8 D9 D12 D14 D24 D25 = 1N4148WHE3: Diode,IFM=300mA,VR=100V,,VRRM=100V,SOD-123,2.85*1.8*1.35mm; Part Number: 30307080; Manufacture 1: MCC美微科
D16-D18 = M7: Diode,Vr=1000V,If=1.0A,Vf=1.1V,DO-214AC,M7,5.26*2.79*0.9mm; Part Number: 30307015; Manufacture 1: 深圳西龙; 代理/分销商: 深圳市长江电子有限公司
DL1-DL3 = HH54PDC12V: 电磁继电器,Us=DC12V,Ui=250V,Ith=3A,GB/T14048.5-2008; Manufacture 1: TAIMING
FB4 FB5 = 1000Ω/0.8A-AEC-Q200: Bead,1000Ω@100MHz,25%,0.8A,1.6x0.8x0.8mm; Part Number: 30319012; Manufacture 1: TDK; Manufacture 1 P/N: MPZ1608S102ATD25; 代理/分销商: 创思（北京）电子技术有限公司
L2 L3 = ACT45C-101-2P-TL000: 共模电感,100uH+50/-30%@100kHz,Max DCR=2.0Ω,4.5x3.2x2.8mm; Part Number: 30310076; Manufacture 1: TDK; 代理/分销商: 创思（北京）电子技术有限公司
LED4-LED6 LED11 = LED-R: LED,普通红; Part Number: 30303001
LED9 = LED-G: LED,普通绿
Q2-Q9 Q21 Q25 Q27 Q54 = 8050: NPN,Vcbo=40V,Vceo=25V,Vebo=6V,IC=1.5A,IB=0.5A,SOT-89,4.6*4.25*1.6mm; Manufacture 1: 江苏长江电子; Manufacture 1 P/N: PXT8550; Part Number: 30306009; 代理/分销商: 四平市吉华高新技术有限公司
Q10 = PBSS5250X: PNP,Vcbo=-50V,Vceo=-50V,Vebo=-5V,IC=-2A,SOT-89,4.6*2.6*1.6mm; Manufacture 1: nexperia; Manufacture 1 P/N: PBSS5250X,115; Part Number: 30306038
Q11 Q13-Q20 Q22-Q24 Q26 Q28-Q40 Q48-Q50 Q55-Q58 = BC817-40-AU: NPN,Vcbo=50V,Vceo=45V,Vebo=5V,IC=500mA,SOT-23,3.04*1.4*1.1mm; Manufacture 1: PANJIT; Part Number: 30306040
Q12 = PBSS4250X: NPN,Vcbo=50V,Vceo=50V,Vebo=5V,IC=2A,IB=0.5A,SOT-89,4.6*2.6*1.6mm; Manufacture 1: nexperia; Manufacture 1 P/N: PBSS4250X,115; Part Number: 30306025
Q41-Q47 Q51-Q53 = 8550: PNP,Vcbo=-40V,Vceo=-25V,Vebo=-5V,IC=-1.5A,SOT-89,4.6*4.25*1.6mm; Manufacture 1: 江苏长江电子; Manufacture 1 P/N: PXT8550SOT-893L200-350; Part Number: 30306008; 代理/分销商: 四平市吉华高新技术有限公司; 元件名称: 贴片三极管8550
R7 R8 R13 R14 R16 R17 R26-R32 R41 R42 R53 R57 R60 R61 R63 R64 R68 R69 R74 R81 R84 R88 R90 R92 R94 R96 R101 R121 R122 R131 R132 R218-R223 R236 R237 = R30R_1206_5%: RES,30R,1/4W,5%,R1206; Part Number: 30304015; Manufacture 1: 风华高科FH; Manufacture 1 P/N: RS06K300JT; 代理/分销商: 四平市吉华高新技术有限公司
R33 R34 = R100K_0402_1%_X: RES,100K,1/16W,1%,R0402; Part Number: 30304361; Manufacture 1: YAGEO; Manufacture 1 P/N: RC0402FR-07100KL; 代理/分销商: 厦门信和达电子有限公司; 元件名称: 贴片电阻100K-0402精密
R35-R37 R103 R106-R111 R123 R198 R205-R210 R229 R230 R232 R238 = R3K3_0805_5%: RES,3K3,1/8W,5%,R0805; Part Number: 30304033; Manufacture 1: 风华高科FH; Manufacture 1 P/N: RS05K332JT; 代理/分销商: 四平市吉华高新技术有限公司
R38-R40 R112-R118 R124 R211-R217 R233-R235 R239 = R10K_0805_5%: RES,10K,1/8W,5%,R0805; Part Number: 30304036; Manufacture 1: 风华高科FH; Manufacture 1 P/N: RS05K103JT; 代理/分销商: 四平市吉华高新技术有限公司
R43 R44 R125-R130 = R1K2_1206_1%_X: RES,1K2,1/4W,1%,R1206; Part Number: 30304432; Manufacture 1: YAGEO; Manufacture 1 P/N: RC1206FR-071K2L; 代理/分销商: 厦门信和达电子有限公司
R45 R55 R65 R71 R119 = R1K2_1206_5%: RES,1K2,1/4W,5%,R1206; Part Number: 30304045; Manufacture 1: 风华高科FH; Manufacture 1 P/N: RS06K122JT; 代理/分销商: 四平市吉华高新技术有限公司
R46 R58 R66 R72 R120 = R33K_0402_5%: RES,33K,1/16W,5%,R0402; Part Number: 30304242; Manufacture 1: 风华高科FH; Manufacture 1 P/N: RC02W333JT; 代理/分销商: 四平市吉华高新技术有限公司
R47 R48 R52 R184-R187 R245 R246 R257 = R150R_1206_5%: RES,150R,1/4W,5%,R1206; Part Number: 30304018; Manufacture 1: 风华高科FH; Manufacture 1 P/N: RS06K151JT; 代理/分销商: 四平市吉华高新技术有限公司; 元件名称: 贴片电阻  150Ω-1206
R49 R50 R247 R248 = R220R_1206_5%: RES,220R,1/8W,5%,R1206; Manufacture 1: 风华高科FH; Manufacture 1 P/N: RS06K221JT; 代理/分销商: 四平市吉华高新技术有限公司
R51 R56 R249 R258 = R10R_1206_5%_X: RES,10R,1/4W,5%,R1206; Part Number: 30304533; Manufacture 1: YAGEO; Manufacture 1 P/N: RC1206JR-0710RL; 代理/分销商: 厦门信和达电子有限公司; 元件名称: 贴片电阻10Ω-1206 X
R54 R86 R135-R138 R263 R264 = R30R_1206_5%: RES,30R,1/4W,5%,R1206; Part Number: 30304015; Manufacture 1: 风华高科FH; Manufacture 1 P/N: RS06K300JT; 代理/分销商: 四平市吉华高新技术有限公司; 元件名称: 贴片电阻  30Ω-1206
R59 R62 R73 R142 R148 R150-R152 R156 R158-R161 R164-R166 R168 R170-R173 R176 R177 R188 R189 R196 R224-R226 R240 R244 R250 R251 R254 R255 = R3K3_0805_5%: RES,3K3,1/8W,5%,R0805; Part Number: 30304033; Manufacture 1: 风华高科FH; Manufacture 1 P/N: RS05K332JT; 代理/分销商: 四平市吉华高新技术有限公司; 元件名称: 贴片电阻 3.3K-0805
R67 R70 R139 R143 R147 R149 R153-R155 R157 R162 R163 R167 R169 R174 R175 R178 R179 R190 R194 R197 R199-R204 R227 R228 R231 R241-R243 R252 R253 R256 R259-R262 = R10K_0603_5%: RES,10K,1/10W,5%,R0603; Part Number: 30304099; Manufacture 1: 风华高科FH; Manufacture 1 P/N: RS03K103JT; 代理/分销商: 四平市吉华高新技术有限公司; 元件名称: 贴片电阻 10K-0603
R75 R104 R105 = R1K5_1206_5%: RES,1K5,1/4W,5%,R1206; Part Number: 30304046; Manufacture 1: 风华高科FH; Manufacture 1 P/N: RS06K152JT; 代理/分销商: 四平市吉华高新技术有限公司
R76 R77 R80 = R330R_1206_5%: RES,330R,1/4W,5%,R1206; Part Number: 30304021; Manufacture 1: 风华高科FH; Manufacture 1 P/N: RS06K331JT; 代理/分销商: 四平市吉华高新技术有限公司
R78 R79 = R150R_1206_5%: RES,150R,1/4W,5%,R1206; Part Number: 30304018; Manufacture 1: 风华高科FH; Manufacture 1 P/N: RS06K151JT; 代理/分销商: 四平市吉华高新技术有限公司
R102 R144-R146 = R1R2W: RES,1R,2W,1%,2WR; Part Number: 30315006; 代理/分销商: 淄博美科电子有限公司; 元件名称: 插件电阻2W1-(AXIAL0.8)
R133 R141 = NC_R0603: NC,R0603
R134 = R1K2_1206_1%: RES,1K2,1/4W,1%,R1206; Part Number: 30304070; Manufacture 1: 风华高科FH; Manufacture 1 P/N: RS06K1201FT; 代理/分销商: 四平市吉华高新技术有限公司; 元件名称: 贴片电阻 1.2K-精密-1206
R140 = NC_R1206: NC,R1206
R180 = R0R_1206_5%: RES,0R,1/4W,5%,R1206; Part Number: 30304011; Manufacture 1: 风华高科FH; Manufacture 1 P/N: RS06000JT; 代理/分销商: 四平市吉华高新技术有限公司; 元件名称: 贴片电阻 0Ω-1206
R181 = R1K_1206_5%: RES,1K,1/4W,5%,R1206; Part Number: 30304044; Manufacture 1: 风华高科FH; Manufacture 1 P/N: RS06K102JT; 代理/分销商: 四平市吉华高新技术有限公司; 元件名称: 贴片电阻 1K-1206
R182 = R2K2_1206_5%: RES,2K2,1/4W,5%,R1206; Part Number: 30304049; Manufacture 1: 风华高科FH; Manufacture 1 P/N: RS06K222JT; 代理/分销商: 四平市吉华高新技术有限公司; 元件名称: 贴片电阻 2.2K-1206
R183 R191 R192 = R3K3_1206_5%: RES,3K3,1/4W,5%,R1206; Part Number: 30304050; Manufacture 1: 风华高科FH; Manufacture 1 P/N: RS06K332JT; 代理/分销商: 四平市吉华高新技术有限公司; 元件名称: 贴片电阻 3.3K-1206
R193 = R200R_1206_1%: RES,200R,1/4W,1%,R1206; Part Number: 30304065; Manufacture 1: 风华高科FH; Manufacture 1 P/N: RS06K2000FT; 代理/分销商: 四平市吉华高新技术有限公司; 元件名称: 贴片电阻 200Ω-精密-1206
R195 = R15K_0603_5%: RES,15K,1/10W,5%,R0603; Manufacture 1: 风华高科FH; Manufacture 1 P/N: RS03K153JT; 代理/分销商: 四平市吉华高新技术有限公司
SP1 = BUZZER: Manufacture 1 P/N: BMT1612H14-42LF; Part Number: 30318007; 代理/分销商: 汉得利（常州）电子股份有限公司
SW1-SW5 = SKPMAPE010: 按键,5.4x1.3x1.28mm; Part Number: 30317008; Manufacture 1: ALPS; 代理/分销商: 天津市稳特电子有限公司
TP15-TP18 = 1.0测试点: 测试点 Φ1.0mm
U5 U8 = TJA1044GT: IC,TJA1044GT,CAN驱动芯片,Vcc=4.75~5.25V,5.0*4.0*1.75mm,SO8; Manufacture 1: NXP; Part Number: 30301358; 代理/分销商: 北京立功致远科技有限公司
U7 U10 = INA214-Q1: IC,INA214-Q1,Vcm=-0.1~26V,Vo=1~60uV,Gain=100V/V,TI,2.15x2.4x1.1mm,SC70 (6); Part Number: 30301243; Manufacture 1 P/N: INA214BQDCKRQ1

## Sheet 07_Lcd-C281-ICU-DS-B-V111.SchDoc: C281-ICU-DS-B-V100
size A3; Date: 2022/07/22; DrawnBy: 佟瑞泽; DocumentNumber: 7; Revision: V100; SheetNumber: 7; SheetTotal: 7
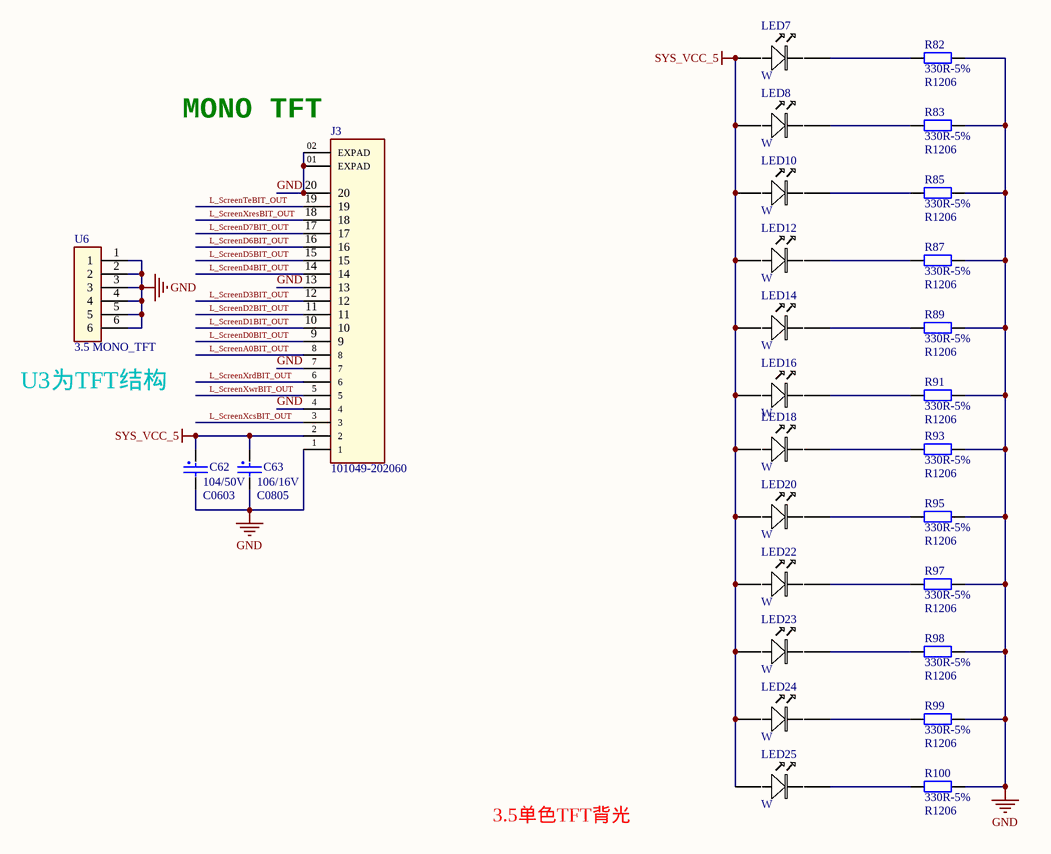
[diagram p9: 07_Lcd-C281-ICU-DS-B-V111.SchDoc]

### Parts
C62  value 104/50V  [C0603]  (hidden comment: 104)
C63  value 106/16V  [C0805]  (hidden comment: 106)
J3  101049-202060  [101049-202060]
LED7  W  [LED]
LED8  W  [LED]
LED10  W  [LED]
LED12  W  [LED]
LED14  W  [LED]
LED16  W  [LED]
LED18  W  [LED]
LED20  W  [LED]
LED22  W  [LED]
LED23  W  [LED]
LED24  W  [LED]
LED25  W  [LED]
R82  value 330R-5%  [R1206]  (hidden comment: 330R)
R83  value 330R-5%  [R1206]  (hidden comment: 330R)
R85  value 330R-5%  [R1206]  (hidden comment: 330R)
R87  value 330R-5%  [R1206]  (hidden comment: 330R)
R89  value 330R-5%  [R1206]  (hidden comment: 330R)
R91  value 330R-5%  [R1206]  (hidden comment: 330R)
R93  value 330R-5%  [R1206]  (hidden comment: 330R)
R95  value 330R-5%  [R1206]  (hidden comment: 330R)
R97  value 330R-5%  [R1206]  (hidden comment: 330R)
R98  value 330R-5%  [R1206]  (hidden comment: 330R)
R99  value 330R-5%  [R1206]  (hidden comment: 330R)
R100  value 330R-5%  [R1206]  (hidden comment: 330R)
U6  3.5 MONO_TFT  [3.5 MONO_TFT]

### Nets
GND: C62.2 C63.2 J3.1 J3.01(EXPAD) J3.02(EXPAD) J3.4 J3.7 J3.13 J3.20 R82.2 R83.2 R85.2 R87.2 R89.2 R91.2 R93.2 R95.2 R97.2 R98.2 R99.2 R100.2 U6.1 U6.2 U6.3 U6.4 U6.5 U6.6
SYS_VCC_5: C62.1 C63.1 J3.2 LED7.1 LED8.1 LED10.1 LED12.1 LED14.1 LED16.1 LED18.1 LED20.1 LED22.1 LED23.1 LED24.1 LED25.1
L_ScreenA0BIT_OUT: J3.8
L_ScreenD0BIT_OUT: J3.9
L_ScreenD1BIT_OUT: J3.10
L_ScreenD2BIT_OUT: J3.11
L_ScreenD3BIT_OUT: J3.12
L_ScreenD4BIT_OUT: J3.14
L_ScreenD5BIT_OUT: J3.15
L_ScreenD6BIT_OUT: J3.16
L_ScreenD7BIT_OUT: J3.17
L_ScreenTeBIT_OUT: J3.19
L_ScreenXcsBIT_OUT: J3.3
L_ScreenXrdBIT_OUT: J3.6
L_ScreenXresBIT_OUT: J3.18
L_ScreenXwrBIT_OUT: J3.5
NetLED7_2: LED7.2 R82.1
NetLED8_2: LED8.2 R83.1
NetLED10_2: LED10.2 R85.1
NetLED12_2: LED12.2 R87.1
NetLED14_2: LED14.2 R89.1
NetLED16_2: LED16.2 R91.1
NetLED18_2: LED18.2 R93.1
NetLED20_2: LED20.2 R95.1
NetLED22_2: LED22.2 R97.1
NetLED23_2: LED23.2 R98.1
NetLED24_2: LED24.2 R99.1
NetLED25_2: LED25.2 R100.1

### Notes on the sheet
- (near J3) MONO TFT
- (near U6) U3为TFT结构
- 3.5单色TFT背光

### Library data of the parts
C62 = C104-50V-C0603: as C40 on sheet 06_Peripheral-C281-ICU-DS-B-V111
C63 = C106-16V-C0805: CAP,106,16V,10%,C0805; Part Number: 30305012; Manufacture 1: FH; Manufacture 1 P/N: 0805X106K160NT; 代理/分销商: 四平市吉华高新技术有限公司
J3 = 101049-202060: Connector,捷康,101049-202060,PITCH=0.5mm,20PIN,H=2.5mm
LED7 LED8 LED10 LED12 LED14 LED16 LED18 LED20 LED22-LED25 = LED-W: LED,冷白; Part Number: 30303039
R82 R83 R85 R87 R89 R91 R93 R95 R97-R100 = R330R_1206_5%: as R76 on sheet 06_Peripheral-C281-ICU-DS-B-V111
U6 = 3.5 MONO_TFT: 3.5 MONO_TFT,带导光罩

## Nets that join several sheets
B+: 03_Connect-C281-ICU-DS-B-V111 (J1.1 J1.2), 06_Peripheral-C281-ICU-DS-B-V111 (12 pins)
GND: 03_Connect-C281-ICU-DS-B-V111 (8 pins), 04_Power-C281-ICU-DS-B-V111 (15 pins), 05_Controller-C281-ICU-DS-B-V111 (30 pins), 06_Peripheral-C281-ICU-DS-B-V111 (136 pins), 07_Lcd-C281-ICU-DS-B-V111 (27 pins)
KL15: 03_Connect-C281-ICU-DS-B-V111 (J1.3 J1.4), 06_Peripheral-C281-ICU-DS-B-V111 (DL3.5 DL3.6 DL3.7 DL3.8)
POWER: 03_Connect-C281-ICU-DS-B-V111 (D1.1 D2.1 D3.1 J4.1), 06_Peripheral-C281-ICU-DS-B-V111 (12 pins)
SYS_VCC_5: 04_Power-C281-ICU-DS-B-V111 (7 pins), 05_Controller-C281-ICU-DS-B-V111 (C20.1 C27.1 FB3.2 FB7.1), 06_Peripheral-C281-ICU-DS-B-V111 (20 pins), 07_Lcd-C281-ICU-DS-B-V111 (15 pins)
VCC12V_SYS: 03_Connect-C281-ICU-DS-B-V111 (D1.2 D2.2 D3.2), 04_Power-C281-ICU-DS-B-V111 (6 pins), 06_Peripheral-C281-ICU-DS-B-V111 (23 pins)
A_IDDQ_KL30: 05_Controller-C281-ICU-DS-B-V111 (U2.59), 06_Peripheral-C281-ICU-DS-B-V111 (C67.1 U7.6)
A_IDDQ_KL30_MCU: 05_Controller-C281-ICU-DS-B-V111 (U2.53), 06_Peripheral-C281-ICU-DS-B-V111 (C57.1 U10.6)
C_CANRX_OUT: 05_Controller-C281-ICU-DS-B-V111 (U2.38), 06_Peripheral-C281-ICU-DS-B-V111 (U8.4)
C_CANTX_OUT: 05_Controller-C281-ICU-DS-B-V111 (U2.37), 06_Peripheral-C281-ICU-DS-B-V111 (U8.1)
CAN2_RX_MCU: 05_Controller-C281-ICU-DS-B-V111 (U2.12), 06_Peripheral-C281-ICU-DS-B-V111 (U5.4)
CAN2_TX_MCU: 05_Controller-C281-ICU-DS-B-V111 (U2.11), 06_Peripheral-C281-ICU-DS-B-V111 (U5.1)
FM_PWM_MCU: 05_Controller-C281-ICU-DS-B-V111 (U2.85), 06_Peripheral-C281-ICU-DS-B-V111 (R142.1 R143.2)
FUEL_RES1_MCU: 05_Controller-C281-ICU-DS-B-V111 (U2.16), 06_Peripheral-C281-ICU-DS-B-V111 (R62.1 R70.2)
FUEL_RES2_MCU: 05_Controller-C281-ICU-DS-B-V111 (U2.22), 06_Peripheral-C281-ICU-DS-B-V111 (R59.1 R67.2)
FUEL_RES3_MCU: 05_Controller-C281-ICU-DS-B-V111 (U2.20), 06_Peripheral-C281-ICU-DS-B-V111 (R73.1 R147.2)
FUEL_RES4_MCU: 05_Controller-C281-ICU-DS-B-V111 (U2.21), 06_Peripheral-C281-ICU-DS-B-V111 (R148.1 R149.2)
HS_CAN1_H: 03_Connect-C281-ICU-DS-B-V111 (J1.23), 06_Peripheral-C281-ICU-DS-B-V111 (C31.1 L3.4 R125.2 R127.2)
HS_CAN1_L: 03_Connect-C281-ICU-DS-B-V111 (J1.24), 06_Peripheral-C281-ICU-DS-B-V111 (C39.1 L3.1 R129.2 R130.2)
HS_CAN2_H: 03_Connect-C281-ICU-DS-B-V111 (J1.26), 06_Peripheral-C281-ICU-DS-B-V111 (C30.1 L2.4 R43.2 R44.2)
HS_CAN2_L: 03_Connect-C281-ICU-DS-B-V111 (J1.27), 06_Peripheral-C281-ICU-DS-B-V111 (C37.1 L2.1 R126.2 R128.2)
Key_DET: 03_Connect-C281-ICU-DS-B-V111 (J1.21), 06_Peripheral-C281-ICU-DS-B-V111 (6 pins)
L_ScreenA0BIT_OUT: 05_Controller-C281-ICU-DS-B-V111 (U2.93), 07_Lcd-C281-ICU-DS-B-V111 (J3.8)
L_ScreenD0BIT_OUT: 05_Controller-C281-ICU-DS-B-V111 (U2.42), 07_Lcd-C281-ICU-DS-B-V111 (J3.9)
L_ScreenD1BIT_OUT: 05_Controller-C281-ICU-DS-B-V111 (U2.43), 07_Lcd-C281-ICU-DS-B-V111 (J3.10)
L_ScreenD2BIT_OUT: 05_Controller-C281-ICU-DS-B-V111 (U2.19), 07_Lcd-C281-ICU-DS-B-V111 (J3.11)
L_ScreenD3BIT_OUT: 05_Controller-C281-ICU-DS-B-V111 (U2.44), 07_Lcd-C281-ICU-DS-B-V111 (J3.12)
L_ScreenD4BIT_OUT: 05_Controller-C281-ICU-DS-B-V111 (U2.45), 07_Lcd-C281-ICU-DS-B-V111 (J3.14)
L_ScreenD5BIT_OUT: 05_Controller-C281-ICU-DS-B-V111 (U2.46), 07_Lcd-C281-ICU-DS-B-V111 (J3.15)
L_ScreenD6BIT_OUT: 05_Controller-C281-ICU-DS-B-V111 (U2.47), 07_Lcd-C281-ICU-DS-B-V111 (J3.16)
L_ScreenD7BIT_OUT: 05_Controller-C281-ICU-DS-B-V111 (U2.48), 07_Lcd-C281-ICU-DS-B-V111 (J3.17)
L_ScreenTeBIT_OUT: 05_Controller-C281-ICU-DS-B-V111 (U2.95), 07_Lcd-C281-ICU-DS-B-V111 (J3.19)
L_ScreenXcsBIT_OUT: 05_Controller-C281-ICU-DS-B-V111 (U2.90), 07_Lcd-C281-ICU-DS-B-V111 (J3.3)
L_ScreenXrdBIT_OUT: 05_Controller-C281-ICU-DS-B-V111 (U2.92), 07_Lcd-C281-ICU-DS-B-V111 (J3.6)
L_ScreenXresBIT_OUT: 05_Controller-C281-ICU-DS-B-V111 (U2.94), 07_Lcd-C281-ICU-DS-B-V111 (J3.18)
L_ScreenXwrBIT_OUT: 05_Controller-C281-ICU-DS-B-V111 (U2.91), 07_Lcd-C281-ICU-DS-B-V111 (J3.5)
LED1_MCU: 05_Controller-C281-ICU-DS-B-V111 (U2.61), 06_Peripheral-C281-ICU-DS-B-V111 (R160.1 R163.2)
LED2_MCU: 05_Controller-C281-ICU-DS-B-V111 (U2.60), 06_Peripheral-C281-ICU-DS-B-V111 (R164.1 R167.2)
LED3_MCU: 05_Controller-C281-ICU-DS-B-V111 (U2.58), 06_Peripheral-C281-ICU-DS-B-V111 (R156.1 R157.2)
LED4_MCU: 05_Controller-C281-ICU-DS-B-V111 (U2.57), 06_Peripheral-C281-ICU-DS-B-V111 (R159.1 R162.2)
LED5_MCU: 05_Controller-C281-ICU-DS-B-V111 (U2.56), 06_Peripheral-C281-ICU-DS-B-V111 (R166.1 R169.2)
RELAY_B+_MCU: 05_Controller-C281-ICU-DS-B-V111 (U2.87), 06_Peripheral-C281-ICU-DS-B-V111 (R151.1 R154.2)
RELAY_KL15_MCU: 05_Controller-C281-ICU-DS-B-V111 (U2.86), 06_Peripheral-C281-ICU-DS-B-V111 (R152.1 R155.2)
RELAY_MCU_B+~: 05_Controller-C281-ICU-DS-B-V111 (U2.88), 06_Peripheral-C281-ICU-DS-B-V111 (R150.1 R153.2)
SD_MODE_MCU: 05_Controller-C281-ICU-DS-B-V111 (U2.100), 06_Peripheral-C281-ICU-DS-B-V111 (R139.1 R141.2)
SW_1: 05_Controller-C281-ICU-DS-B-V111 (U2.68), 06_Peripheral-C281-ICU-DS-B-V111 (C40.1 R46.2)
SW_2: 05_Controller-C281-ICU-DS-B-V111 (U2.3), 06_Peripheral-C281-ICU-DS-B-V111 (C49.1 R120.2)
SW_3: 05_Controller-C281-ICU-DS-B-V111 (U2.67), 06_Peripheral-C281-ICU-DS-B-V111 (C45.1 R66.2)
SW_4: 05_Controller-C281-ICU-DS-B-V111 (U2.66), 06_Peripheral-C281-ICU-DS-B-V111 (C47.1 R72.2)
SW_5: 05_Controller-C281-ICU-DS-B-V111 (U2.65), 06_Peripheral-C281-ICU-DS-B-V111 (C42.1 R58.2)
TEM_RES1_MCU: 05_Controller-C281-ICU-DS-B-V111 (U2.98), 06_Peripheral-C281-ICU-DS-B-V111 (R250.1 R256.2)
TEM_RES2_MCU: 05_Controller-C281-ICU-DS-B-V111 (U2.99), 06_Peripheral-C281-ICU-DS-B-V111 (R251.1 R259.2)
TEM_RES3_MCU: 05_Controller-C281-ICU-DS-B-V111 (U2.83), 06_Peripheral-C281-ICU-DS-B-V111 (R254.1 R261.2)
TEM_RES4_MCU: 05_Controller-C281-ICU-DS-B-V111 (U2.84), 06_Peripheral-C281-ICU-DS-B-V111 (R255.1 R262.2)
按键1_MCU: 05_Controller-C281-ICU-DS-B-V111 (U2.6), 06_Peripheral-C281-ICU-DS-B-V111 (R172.1 R174.2)
按键2_MCU: 05_Controller-C281-ICU-DS-B-V111 (U2.7), 06_Peripheral-C281-ICU-DS-B-V111 (R173.1 R175.2)
按键3_MCU: 05_Controller-C281-ICU-DS-B-V111 (U2.8), 06_Peripheral-C281-ICU-DS-B-V111 (R177.1 R179.2)
按键4_MCU: 05_Controller-C281-ICU-DS-B-V111 (U2.9), 06_Peripheral-C281-ICU-DS-B-V111 (R176.1 R178.2)
按键5_MCU: 05_Controller-C281-ICU-DS-B-V111 (U2.13), 06_Peripheral-C281-ICU-DS-B-V111 (R189.1 R194.2)
按键6_MCU: 05_Controller-C281-ICU-DS-B-V111 (U2.14), 06_Peripheral-C281-ICU-DS-B-V111 (R188.1 R190.2)
正控_1: 03_Connect-C281-ICU-DS-B-V111 (J1.11), 06_Peripheral-C281-ICU-DS-B-V111 (R53.2 R57.2)
正控_1_MCU: 05_Controller-C281-ICU-DS-B-V111 (U2.80), 06_Peripheral-C281-ICU-DS-B-V111 (R161.2 R199.2)
正控_2: 03_Connect-C281-ICU-DS-B-V111 (J1.12), 06_Peripheral-C281-ICU-DS-B-V111 (R60.2 R61.2)
正控_2_MCU: 05_Controller-C281-ICU-DS-B-V111 (U2.69), 06_Peripheral-C281-ICU-DS-B-V111 (R165.2 R200.2)
正控_3: 03_Connect-C281-ICU-DS-B-V111 (J1.13), 06_Peripheral-C281-ICU-DS-B-V111 (R63.2 R64.2)
正控_3_MCU: 05_Controller-C281-ICU-DS-B-V111 (U2.64), 06_Peripheral-C281-ICU-DS-B-V111 (R168.2 R201.2)
正控_4: 03_Connect-C281-ICU-DS-B-V111 (J1.14), 06_Peripheral-C281-ICU-DS-B-V111 (R68.2 R69.2)
正控_4_MCU: 05_Controller-C281-ICU-DS-B-V111 (U2.63), 06_Peripheral-C281-ICU-DS-B-V111 (R170.2 R202.2)
正控_5: 03_Connect-C281-ICU-DS-B-V111 (J1.15), 06_Peripheral-C281-ICU-DS-B-V111 (R81.2 R84.2)
正控_5_MCU: 05_Controller-C281-ICU-DS-B-V111 (U2.62), 06_Peripheral-C281-ICU-DS-B-V111 (R171.2 R203.2)
正控_6: 03_Connect-C281-ICU-DS-B-V111 (J1.16), 06_Peripheral-C281-ICU-DS-B-V111 (R131.2 R132.2)
正控_6_MCU: 05_Controller-C281-ICU-DS-B-V111 (U2.55), 06_Peripheral-C281-ICU-DS-B-V111 (R196.2 R204.2)
正控_7: 03_Connect-C281-ICU-DS-B-V111 (J1.17), 06_Peripheral-C281-ICU-DS-B-V111 (R41.2 R42.2)
正控_7_MCU: 05_Controller-C281-ICU-DS-B-V111 (U2.54), 06_Peripheral-C281-ICU-DS-B-V111 (R158.2 R197.2)
正控_8: 03_Connect-C281-ICU-DS-B-V111 (J1.18), 06_Peripheral-C281-ICU-DS-B-V111 (R222.2 R223.2)
正控_8_MCU: 05_Controller-C281-ICU-DS-B-V111 (U2.50), 06_Peripheral-C281-ICU-DS-B-V111 (R226.2 R231.2)
正控_9: 03_Connect-C281-ICU-DS-B-V111 (J1.19), 06_Peripheral-C281-ICU-DS-B-V111 (R218.2 R219.2)
正控_9_MCU: 05_Controller-C281-ICU-DS-B-V111 (U2.49), 06_Peripheral-C281-ICU-DS-B-V111 (R224.2 R227.2)
正控_10: 03_Connect-C281-ICU-DS-B-V111 (J1.20), 06_Peripheral-C281-ICU-DS-B-V111 (R220.2 R221.2)
正控_10_MCU: 05_Controller-C281-ICU-DS-B-V111 (U2.40), 06_Peripheral-C281-ICU-DS-B-V111 (R225.2 R228.2)
水温: 03_Connect-C281-ICU-DS-B-V111 (J1.7), 06_Peripheral-C281-ICU-DS-B-V111 (R245.1 R247.1 R257.1 R263.1)
燃油: 03_Connect-C281-ICU-DS-B-V111 (J1.8), 06_Peripheral-C281-ICU-DS-B-V111 (R47.1 R49.1 R52.1 R54.1)
负控_1: 03_Connect-C281-ICU-DS-B-V111 (J1.31), 06_Peripheral-C281-ICU-DS-B-V111 (R26.2 R27.2)
负控_1_MCU: 05_Controller-C281-ICU-DS-B-V111 (U2.75), 06_Peripheral-C281-ICU-DS-B-V111 (R103.2 R112.2)
负控_2: 03_Connect-C281-ICU-DS-B-V111 (J1.32), 06_Peripheral-C281-ICU-DS-B-V111 (R28.2 R29.2)
负控_2_MCU: 05_Controller-C281-ICU-DS-B-V111 (U2.74), 06_Peripheral-C281-ICU-DS-B-V111 (R106.2 R113.2)
负控_3: 03_Connect-C281-ICU-DS-B-V111 (J1.33), 06_Peripheral-C281-ICU-DS-B-V111 (R30.2 R31.2)
负控_3_MCU: 05_Controller-C281-ICU-DS-B-V111 (U2.73), 06_Peripheral-C281-ICU-DS-B-V111 (R107.2 R114.2)
负控_4: 03_Connect-C281-ICU-DS-B-V111 (J1.34), 06_Peripheral-C281-ICU-DS-B-V111 (R32.2 R74.2)
负控_4_MCU: 05_Controller-C281-ICU-DS-B-V111 (U2.72), 06_Peripheral-C281-ICU-DS-B-V111 (R108.2 R115.2)
负控_5: 03_Connect-C281-ICU-DS-B-V111 (J1.35), 06_Peripheral-C281-ICU-DS-B-V111 (R88.2 R90.2)
负控_5_MCU: 05_Controller-C281-ICU-DS-B-V111 (U2.71), 06_Peripheral-C281-ICU-DS-B-V111 (R109.2 R116.2)
负控_6: 03_Connect-C281-ICU-DS-B-V111 (J1.36), 06_Peripheral-C281-ICU-DS-B-V111 (R92.2 R94.2)
负控_6_MCU: 05_Controller-C281-ICU-DS-B-V111 (U2.70), 06_Peripheral-C281-ICU-DS-B-V111 (R110.2 R117.2)
负控_7: 03_Connect-C281-ICU-DS-B-V111 (J1.37), 06_Peripheral-C281-ICU-DS-B-V111 (R96.2 R101.2)
负控_7_MCU: 05_Controller-C281-ICU-DS-B-V111 (U2.81), 06_Peripheral-C281-ICU-DS-B-V111 (R111.2 R118.2)
负控_8: 03_Connect-C281-ICU-DS-B-V111 (J1.38), 06_Peripheral-C281-ICU-DS-B-V111 (R7.2 R8.2)
负控_8_MCU: 05_Controller-C281-ICU-DS-B-V111 (U2.1), 06_Peripheral-C281-ICU-DS-B-V111 (R35.2 R38.2)
负控_9: 03_Connect-C281-ICU-DS-B-V111 (J1.39), 06_Peripheral-C281-ICU-DS-B-V111 (R13.2 R14.2)
负控_9_MCU: 05_Controller-C281-ICU-DS-B-V111 (U2.2), 06_Peripheral-C281-ICU-DS-B-V111 (R36.2 R39.2)
负控_10: 03_Connect-C281-ICU-DS-B-V111 (J1.40), 06_Peripheral-C281-ICU-DS-B-V111 (R16.2 R17.2)
负控_10_MCU: 05_Controller-C281-ICU-DS-B-V111 (U2.39), 06_Peripheral-C281-ICU-DS-B-V111 (R37.2 R40.2)
车速_IOC: 03_Connect-C281-ICU-DS-B-V111 (J1.29), 06_Peripheral-C281-ICU-DS-B-V111 (R240.1 R241.2)
车速_MCU_IOC: 05_Controller-C281-ICU-DS-B-V111 (U2.4), 06_Peripheral-C281-ICU-DS-B-V111 (C10.1 R242.1)
车速_PWM: 03_Connect-C281-ICU-DS-B-V111 (J1.9), 06_Peripheral-C281-ICU-DS-B-V111 (R121.2 R122.2)
车速_PWM_MCU: 05_Controller-C281-ICU-DS-B-V111 (U2.17), 06_Peripheral-C281-ICU-DS-B-V111 (R123.2 R124.2)
转速_IOC: 03_Connect-C281-ICU-DS-B-V111 (J1.30), 06_Peripheral-C281-ICU-DS-B-V111 (R244.1 R252.2)
转速_MCU_IOC: 05_Controller-C281-ICU-DS-B-V111 (U2.5), 06_Peripheral-C281-ICU-DS-B-V111 (C16.1 R253.1)
转速_PWM: 03_Connect-C281-ICU-DS-B-V111 (J1.10), 06_Peripheral-C281-ICU-DS-B-V111 (R236.2 R237.2)
转速_PWM_MCU: 05_Controller-C281-ICU-DS-B-V111 (U2.15), 06_Peripheral-C281-ICU-DS-B-V111 (R238.2 R239.2)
